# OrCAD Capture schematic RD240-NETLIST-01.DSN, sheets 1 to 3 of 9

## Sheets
1 9: size A3
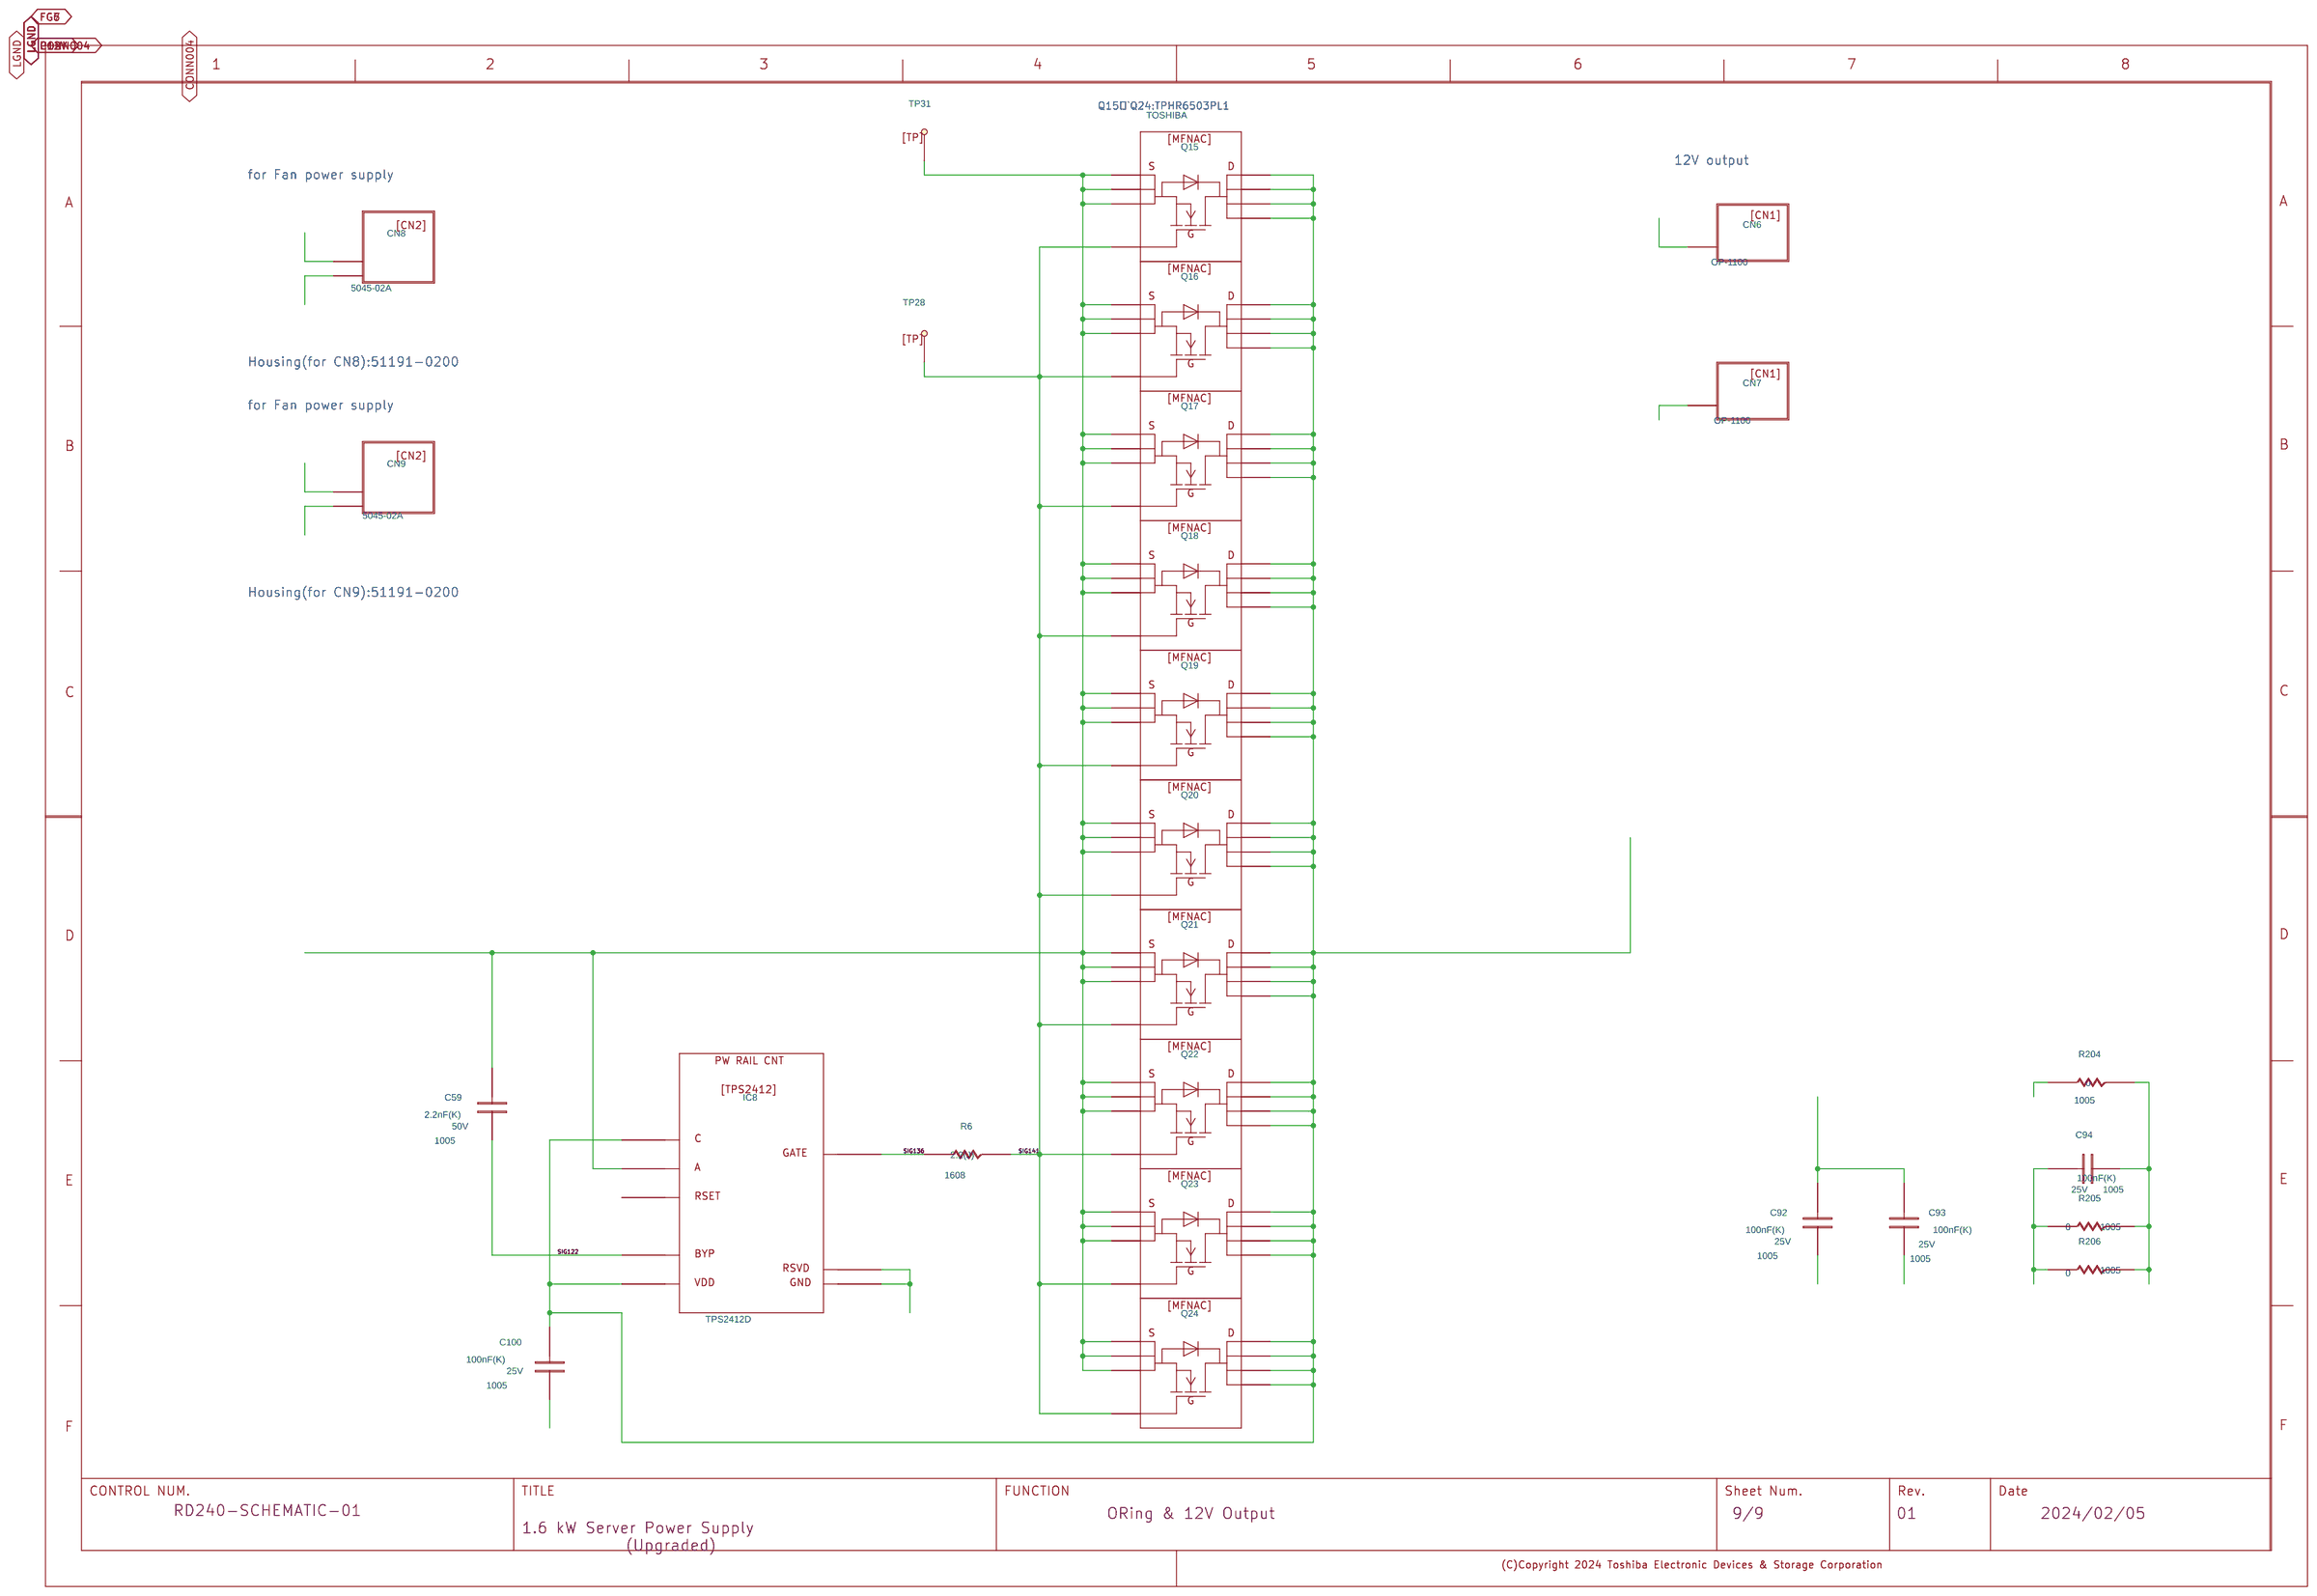
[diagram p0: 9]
2 8: size A3
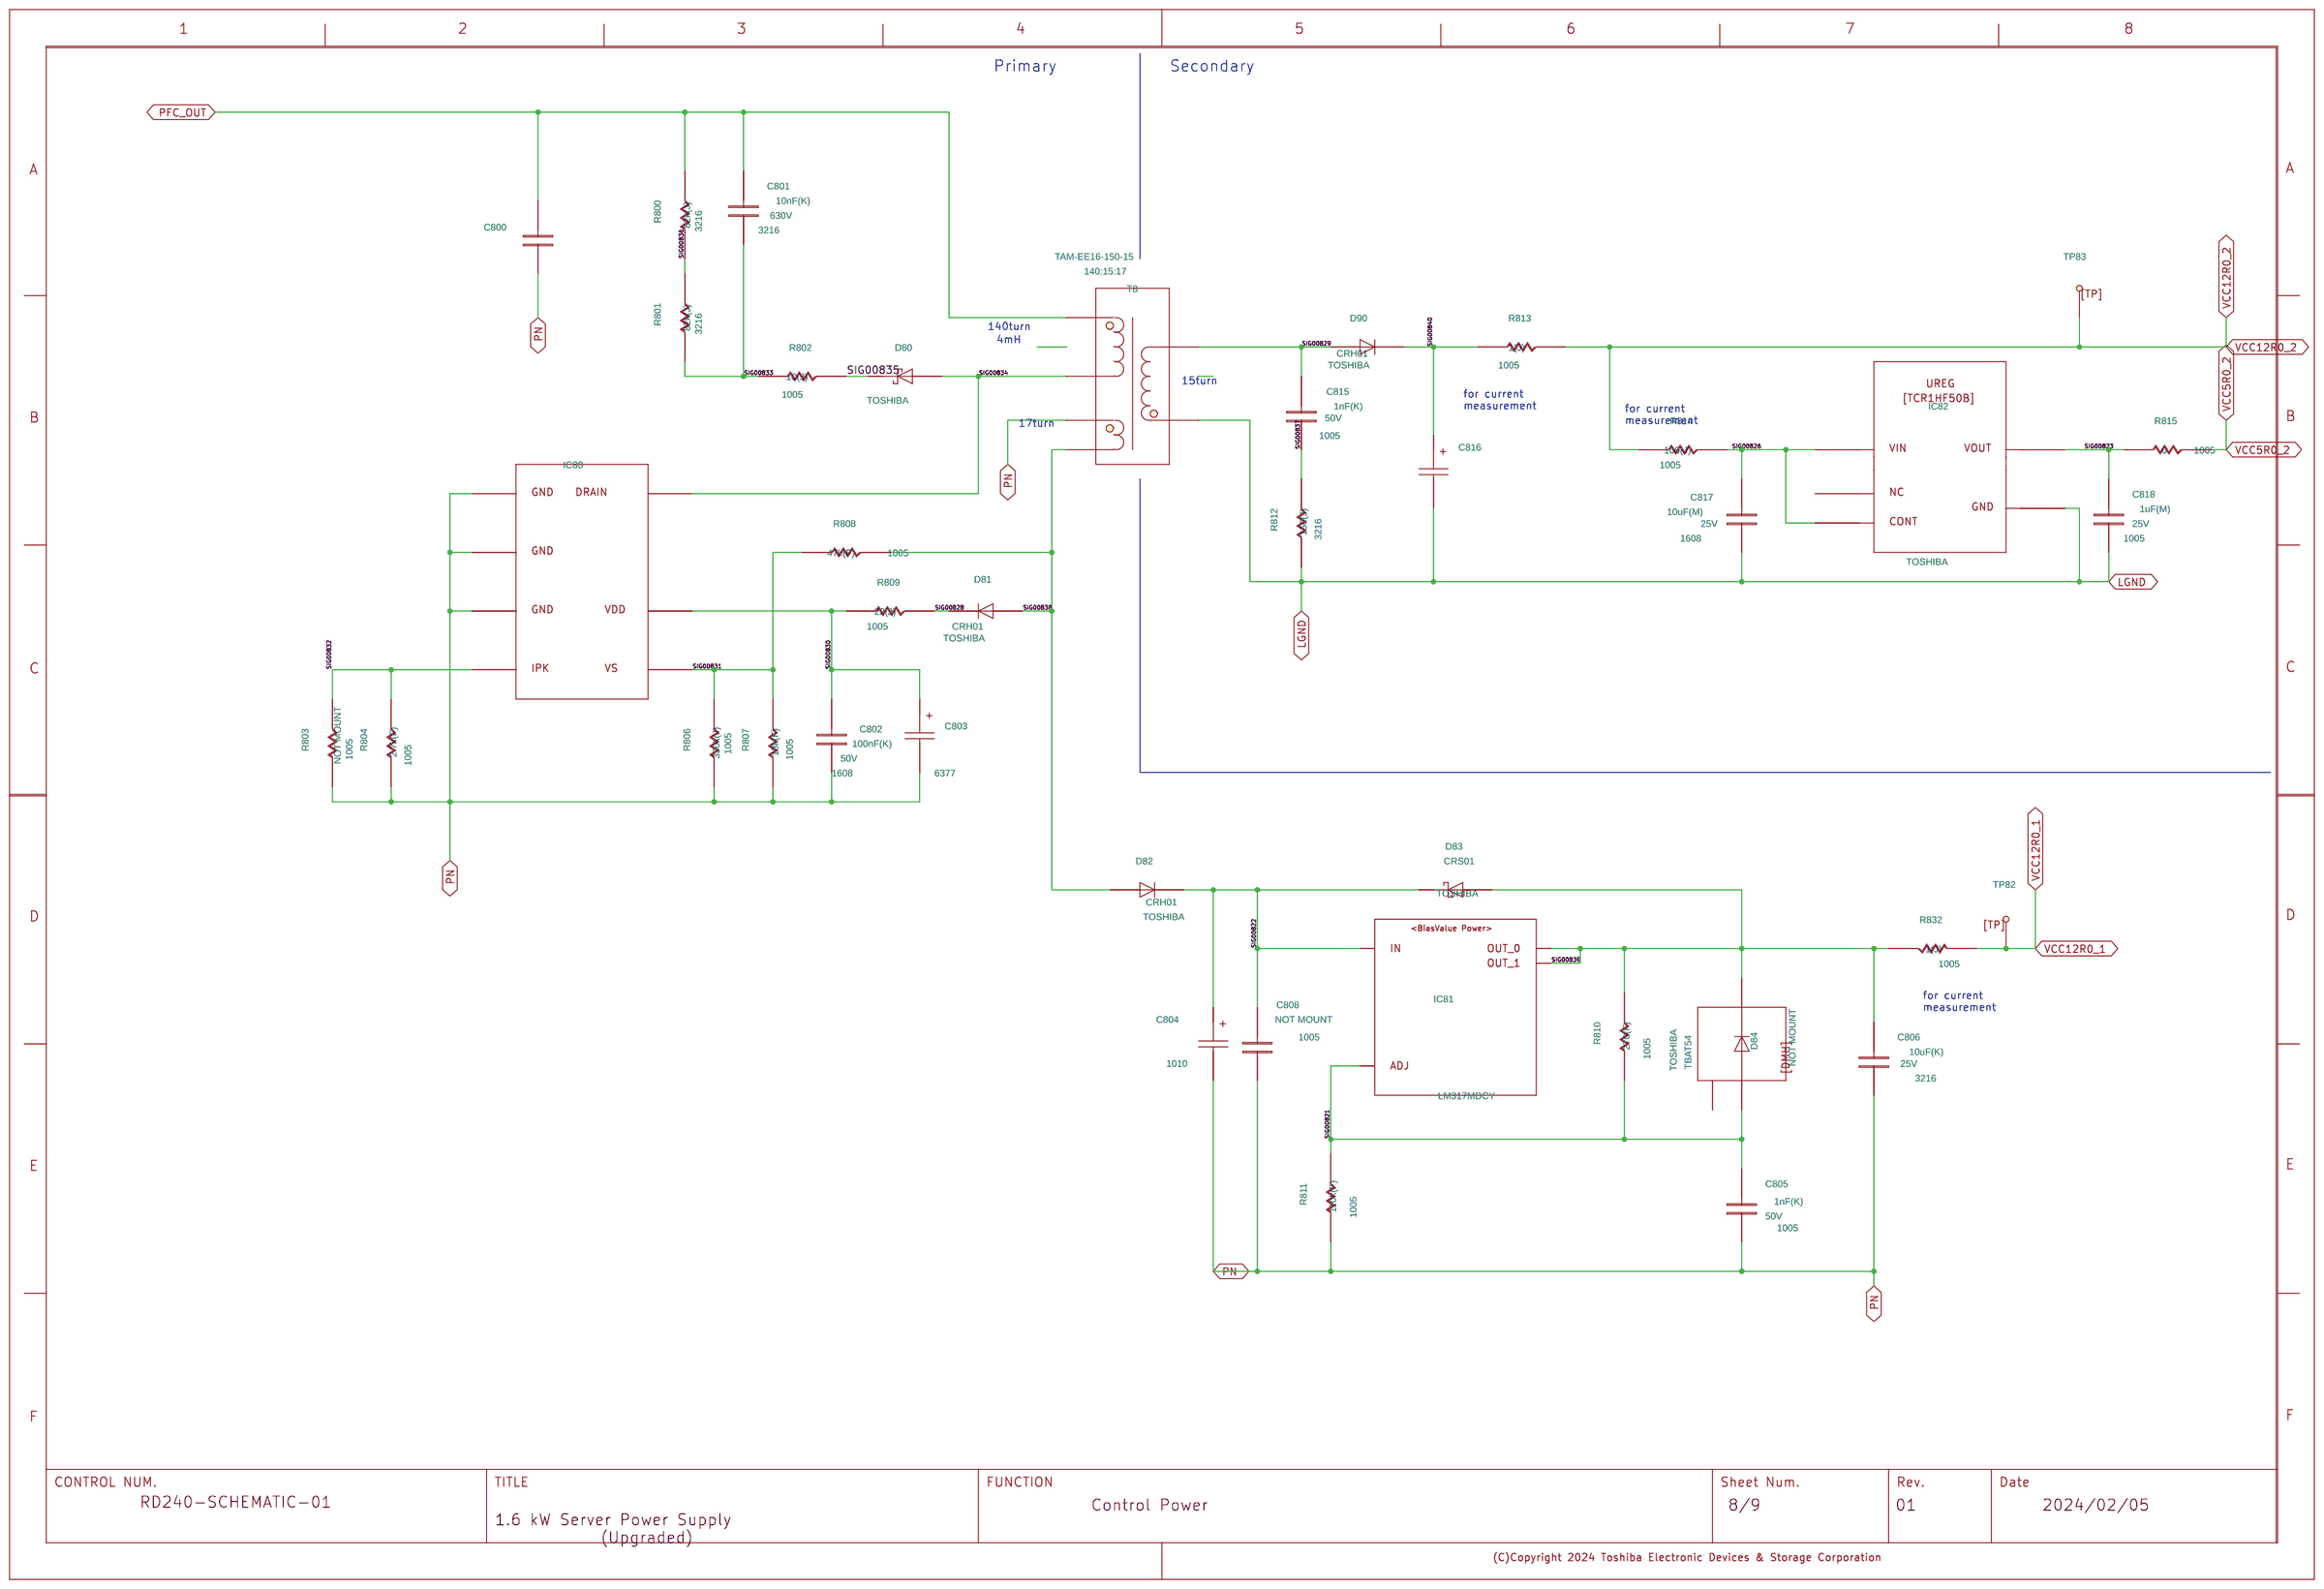
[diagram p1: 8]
3 7: size A3
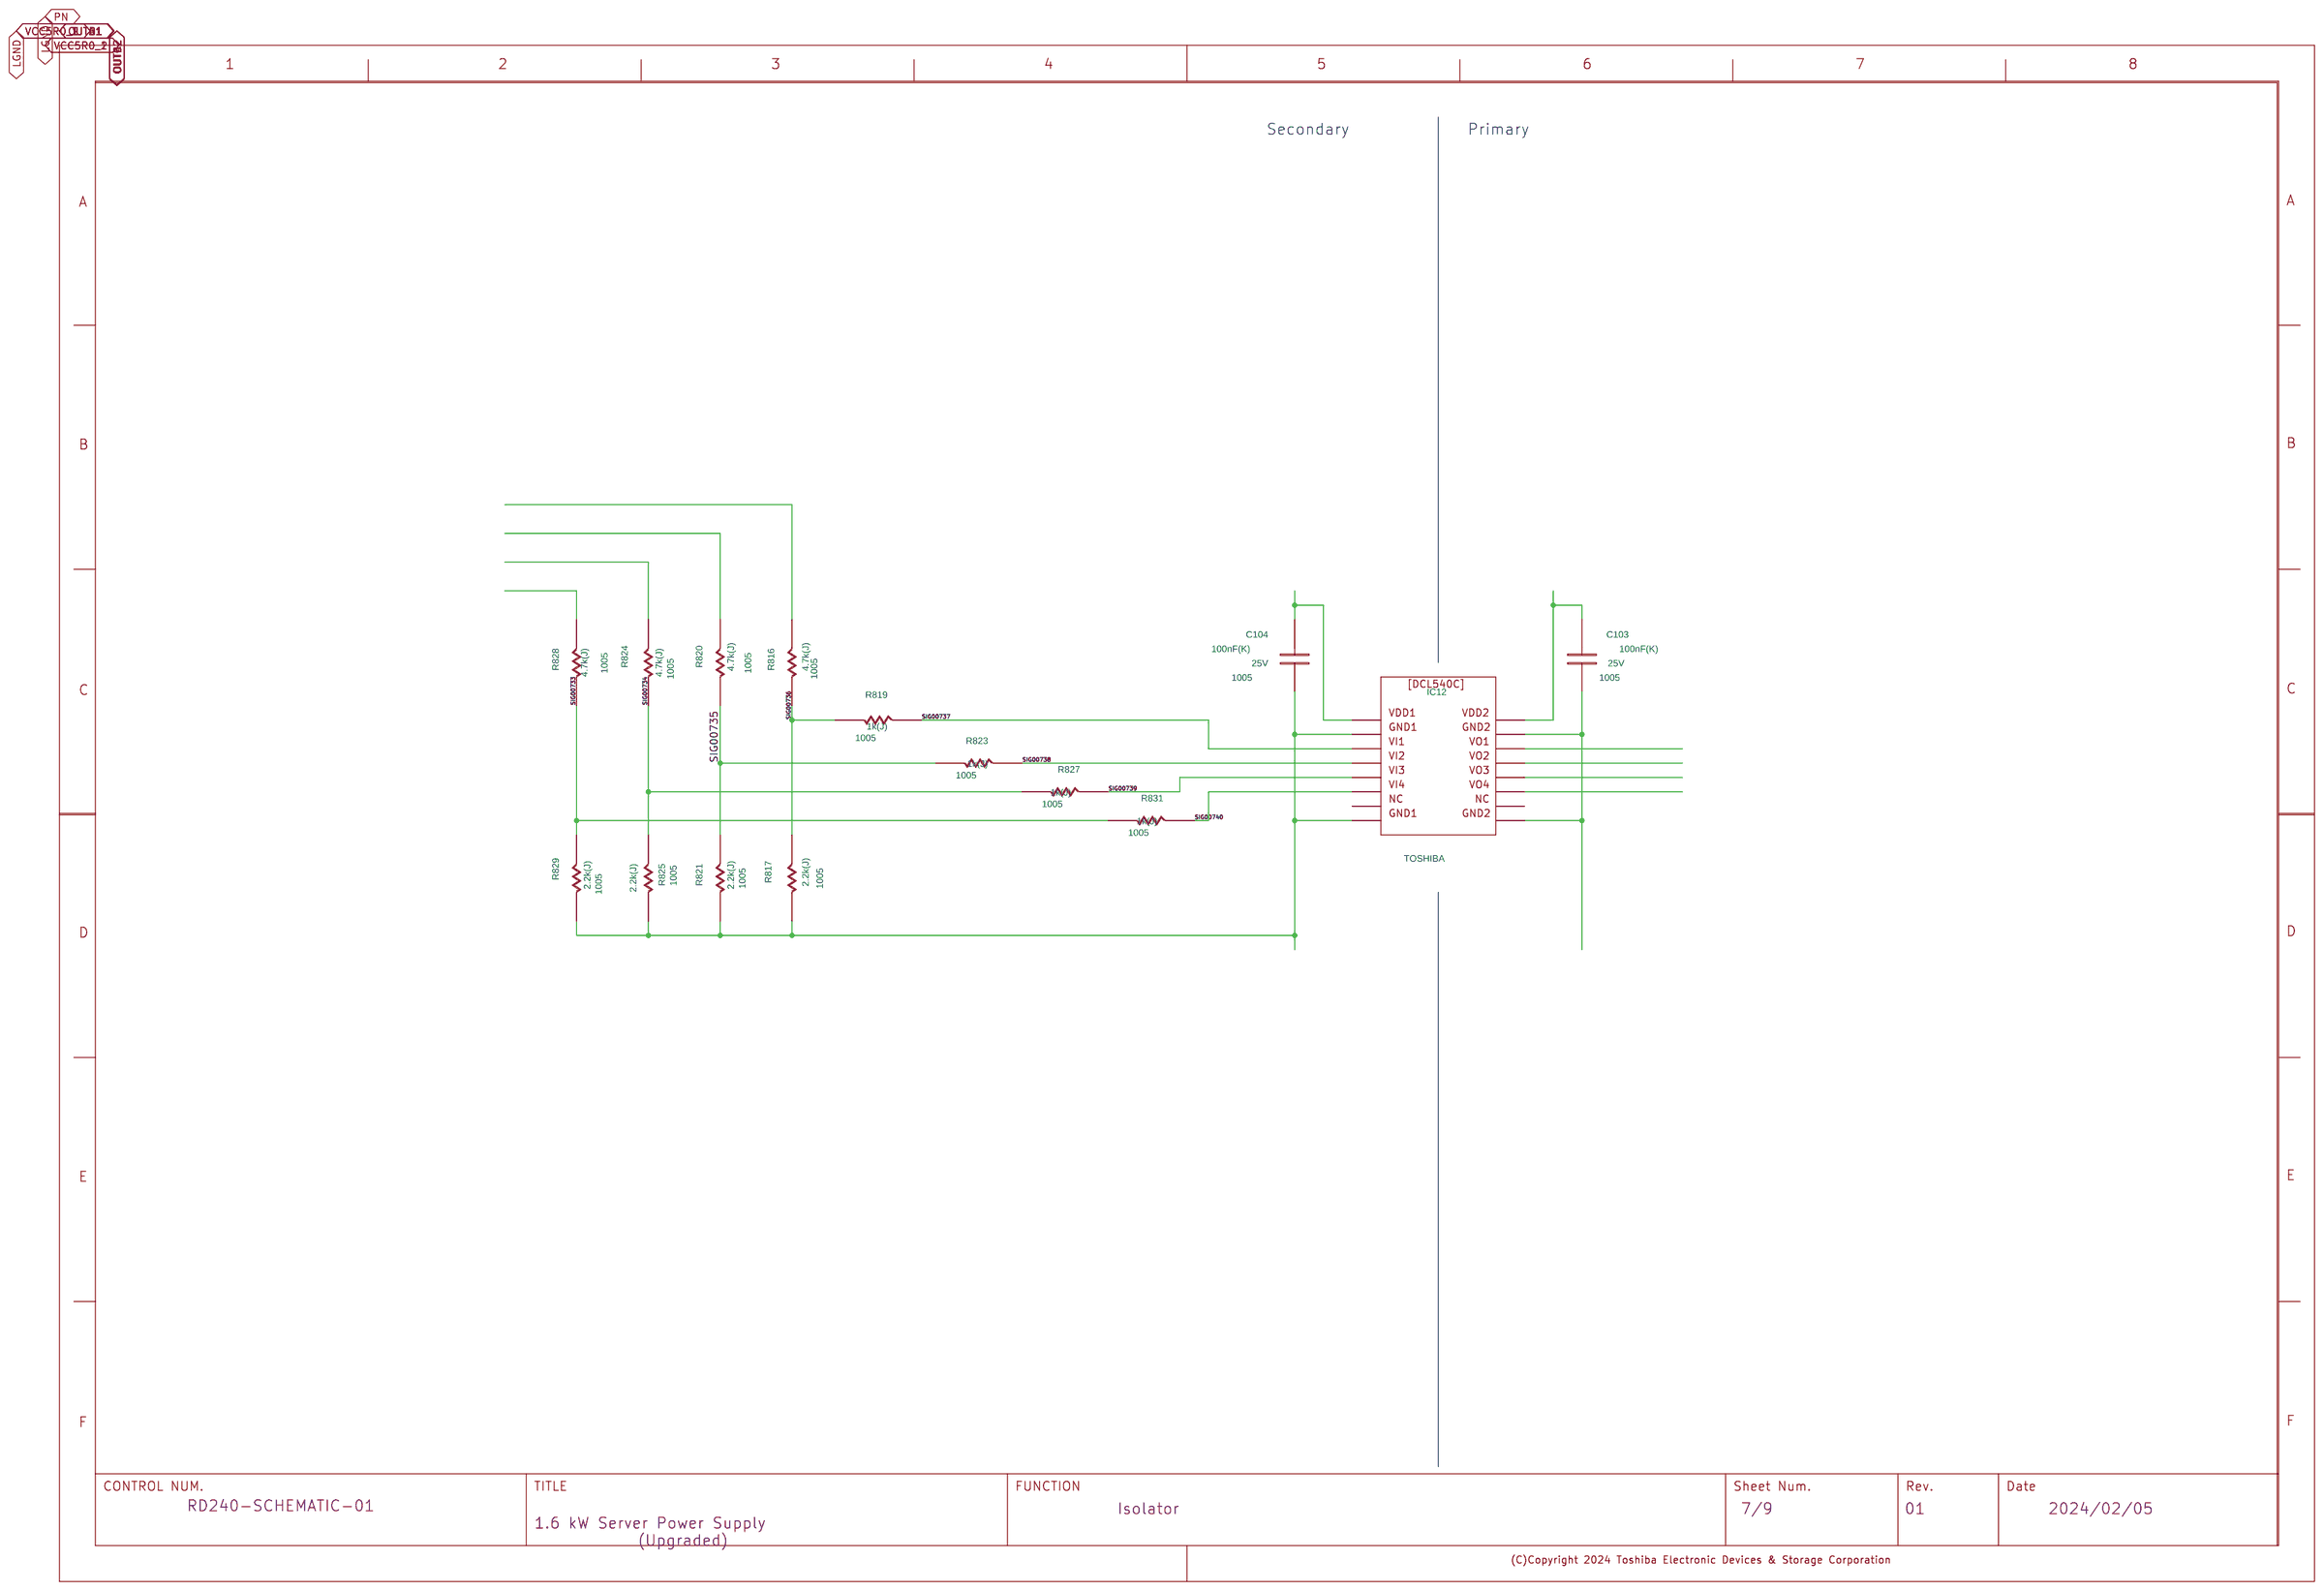
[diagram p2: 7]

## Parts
sheet 7
C103  C
C104  C
IC12  DCL540C01
R816  R
R817  R
R819  R
R820  R
R821  R
R823  R
R824  R
R825  R
R827  R
R828  R
R829  R
R831  R
U?#2  WAKU_DEF100
sheet 8
C800  ECWF6104JL
C801  C
C802  C
C803  EMLA350ARA220MF61G
C804  EMLA350ARA331MJA0G
C805  C
C806  C
C808  C
C815  C
C816  EMLA250ARA221MHA0G
C817  C
C818  C
D80  CRF03A
D81  D
D82  D
D83  SBD
D84  DMH
D90  D
IC80  UCC28910
IC81  LM317_TRANS  [DCY0004A_N]
IC82  TCR1HF50B
R800  R
R801  R
R802  R
R803  R
R804  R
R806  R
R807  R
R808  R
R809  R
R810  R
R811  R
R812  R
R813  R
R814  R
R815  R
R832  R
T8  YB_03317A
TP82  TP
TP83  TP
U?#1  WAKU_DEF100
sheet 9
C59  C
C92  C
C93  C
C94  C
C100  C
CN6  CN1
CN7  CN1
CN8  CN2
CN9  CN2
IC8  L2412
Q15  TPHR6503PL1_8PIN
Q16  TPHR6503PL1_8PIN
Q17  TPHR6503PL1_8PIN
Q18  TPHR6503PL1_8PIN
Q19  TPHR6503PL1_8PIN
Q20  TPHR6503PL1_8PIN
Q21  TPHR6503PL1_8PIN
Q22  TPHR6503PL1_8PIN
Q23  TPHR6503PL1_8PIN
Q24  TPHR6503PL1_8PIN
R6  R
R204  R
R205  R
R206  R
TP28  TP
TP31  TP
U?#9  WAKU_DEF100

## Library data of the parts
C103 = C: ADSCNVFLAG: ON; ADSCOMPONENTNAME: C_1005; ADSMODELNAME: s_GRM155R71E104KE14D; AUTHOR: sptcae13; CAPACITANCETOLE: K; CDMASTERCADCELG: KC0005; CHIPSIZE: 1005; COMP: PRT_52; COMPONENTTYPE: 4; DATE: 2024/01/31; FNLEADFREETHET1GT2GMCTH1: N_N_N; GCOUNT: 1; ICX_PART_MODEL: CON_100N; INSTANCENAME: cmp183; MAKER: TDK; MAXGCOUNT: 1; NOMINALCAPACITA: 100n; OUMECLASSIFICATION: ƒZƒ‰ƒ~ƒbƒNƒRƒ“ƒfƒ“ƒT; OUMEMAKER: MRT ºc»ì; OUMEMAKERKATAMEI: GRM155R71E104KE14D; QUADMODEL: CON_100N; RATEDVOLTAGE: 25; SAVECOUNT: 0; SIZECODESMD: 1005; SQ_PART_MODEL: CON_100N; TIME: 13:58:26; UPDATEDATE: 2024/01/31; UPDATETIME: 13:58:26; UPDATEUSER: sptcae13; VAL1: 100nF(K); VAL2: 25V; VAL3: C1005X7R1E104K050BB
C104 = C: ADSCNVFLAG: ON; ADSCOMPONENTNAME: C_1005; ADSMODELNAME: s_GRM155R71E104KE14D; AUTHOR: sptcae13; CAPACITANCETOLE: K; CDMASTERCADCELG: KC0005; CHIPSIZE: 1005; COMP: PRT_52; COMPONENTTYPE: 4; DATE: 2024/01/31; FNLEADFREETHET1GT2GMCTH1: N_N_N; GCOUNT: 1; ICX_PART_MODEL: CON_100N; INSTANCENAME: cmp178; MAKER: TDK; MAXGCOUNT: 1; NOMINALCAPACITA: 100n; OUMECLASSIFICATION: ƒZƒ‰ƒ~ƒbƒNƒRƒ“ƒfƒ“ƒT; OUMEMAKER: MRT ºc»ì; OUMEMAKERKATAMEI: GRM155R71E104KE14D; QUADMODEL: CON_100N; RATEDVOLTAGE: 25; SAVECOUNT: 0; SIZECODESMD: 1005; SQ_PART_MODEL: CON_100N; TIME: 13:58:26; UPDATEDATE: 2024/01/31; UPDATETIME: 13:58:26; UPDATEUSER: sptcae13; VAL1: 100nF(K); VAL2: 25V; VAL3: C1005X7R1E104K050BB
IC12 = DCL540C01: ALLGREEN: 0:O[; CDMASTERCADCELG: DI9G1D; COMPONENTTYPE: 4; FNAPPROVALRESUG: B:i(GREEN); FNCANCELLATIONG: 0:Žg—p‰Â; FNENVIRONMANTRG: 0:Žg—p–³; FNLEADFREETHET1GT2GMCTH1: 2_0_N; FUNCTION: FXD; GANSWERREV: 6; GCOUNT: 1; INSTANCENAME: cmp194; KIND: VRGL; MAXGCOUNT: 1; MOUNTINGFORMSMD: SMD; OUMECLASSIFICATION: M[^; OUMEMAKER: ROH [; OUMEMAKERKATAMEI: BH15LB1WG-TR; OUMEPARTTYPE: IC; PMPRODUCTSTYPEG: TV2; USERCOMPTEXT3: TOSHIBA
R816 = R: ADSMODELNAME: s_RC0402FR_071KL; ALLGREEN: 0:O[; CDMASTERCADCELG: KC0005; CHIPSIZE: 1608; COMPONENTTYPE: 4; FNAPPROVALRESUG: B:i(GREEN); FNCANCELLATIONG: 0:Žg—p‰Â; FNENVIRONMANTRG: 1:gpL(K§ÎÛO); FNLEADFREETHET1GT2GMCTH1: 2_2_N; GANSWERREV: 8; GCOUNT: 1; INSTANCENAME: cmp288; MAKER: PANASONIC; MAXGCOUNT: 1; MOUNTINGFORMSMD: SMD; NOMINALRESISTAN: 1K; OUMECLASSIFICATION: \ÊÀpÅèïRí; OUMEMAKER: YGO ƒ„ƒQƒI; OUMEMAKERKATAMEI: RC0402FR-071KL; PMPRODUCTSTYPEG: HD1; POWERRATING: 63m; QUADMODEL: RES_1K; RESISTANCETOLER: F; SAVECOUNT: 0; SIZECODESMD: 1005; VAL1: 4.7k(J); VAL2: 63mW; VAL3: RK73B1ERTTP472J
R817 = R: ADSMODELNAME: s_RC0402FR_071KL; ALLGREEN: 0:O[; CDMASTERCADCELG: KC0005; CHIPSIZE: 1608; COMPONENTTYPE: 4; FNAPPROVALRESUG: B:i(GREEN); FNCANCELLATIONG: 0:Žg—p‰Â; FNENVIRONMANTRG: 1:gpL(K§ÎÛO); FNLEADFREETHET1GT2GMCTH1: 2_2_N; GANSWERREV: 8; GCOUNT: 1; INSTANCENAME: cmp284; MAKER: PANASONIC; MAXGCOUNT: 1; MOUNTINGFORMSMD: SMD; NOMINALRESISTAN: 1K; OUMECLASSIFICATION: \ÊÀpÅèïRí; OUMEMAKER: YGO ƒ„ƒQƒI; OUMEMAKERKATAMEI: RC0402FR-071KL; PMPRODUCTSTYPEG: HD1; POWERRATING: 63m; QUADMODEL: RES_1K; RESISTANCETOLER: F; SAVECOUNT: 0; SIZECODESMD: 1005; VAL1: 2.2k(J); VAL2: 63mW; VAL3: RK73B1ERTTP222J
R819 = R: ADSMODELNAME: s_RC0402FR_071KL; ALLGREEN: 0:O[; CDMASTERCADCELG: KC0005; CHIPSIZE: 1608; COMPONENTTYPE: 4; FNAPPROVALRESUG: B:i(GREEN); FNCANCELLATIONG: 0:Žg—p‰Â; FNENVIRONMANTRG: 1:gpL(K§ÎÛO); FNLEADFREETHET1GT2GMCTH1: 2_2_N; GANSWERREV: 8; GCOUNT: 1; INSTANCENAME: cmp222; MAKER: PANASONIC; MAXGCOUNT: 1; MOUNTINGFORMSMD: SMD; NOMINALRESISTAN: 1K; OUMECLASSIFICATION: \ÊÀpÅèïRí; OUMEMAKER: YGO ƒ„ƒQƒI; OUMEMAKERKATAMEI: RC0402FR-071KL; PMPRODUCTSTYPEG: HD1; POWERRATING: 63m; QUADMODEL: RES_1K; RESISTANCETOLER: F; SAVECOUNT: 0; SIZECODESMD: 1005; VAL1: 1k(J); VAL2: 63mW; VAL3: RK73K1ETP102J
R820 = R: ADSMODELNAME: s_RC0402FR_071KL; ALLGREEN: 0:O[; CDMASTERCADCELG: KC0005; CHIPSIZE: 1608; COMPONENTTYPE: 4; FNAPPROVALRESUG: B:i(GREEN); FNCANCELLATIONG: 0:Žg—p‰Â; FNENVIRONMANTRG: 1:gpL(K§ÎÛO); FNLEADFREETHET1GT2GMCTH1: 2_2_N; GANSWERREV: 8; GCOUNT: 1; INSTANCENAME: cmp291; MAKER: PANASONIC; MAXGCOUNT: 1; MOUNTINGFORMSMD: SMD; NOMINALRESISTAN: 1K; OUMECLASSIFICATION: \ÊÀpÅèïRí; OUMEMAKER: YGO ƒ„ƒQƒI; OUMEMAKERKATAMEI: RC0402FR-071KL; PMPRODUCTSTYPEG: HD1; POWERRATING: 63m; QUADMODEL: RES_1K; RESISTANCETOLER: F; SAVECOUNT: 0; SIZECODESMD: 1005; VAL1: 4.7k(J); VAL2: 63mW; VAL3: RK73B1ERTTP472J
R821 = R: ADSMODELNAME: s_RC0402FR_071KL; ALLGREEN: 0:O[; CDMASTERCADCELG: KC0005; CHIPSIZE: 1608; COMPONENTTYPE: 4; FNAPPROVALRESUG: B:i(GREEN); FNCANCELLATIONG: 0:Žg—p‰Â; FNENVIRONMANTRG: 1:gpL(K§ÎÛO); FNLEADFREETHET1GT2GMCTH1: 2_2_N; GANSWERREV: 8; GCOUNT: 1; INSTANCENAME: cmp285; MAKER: PANASONIC; MAXGCOUNT: 1; MOUNTINGFORMSMD: SMD; NOMINALRESISTAN: 1K; OUMECLASSIFICATION: \ÊÀpÅèïRí; OUMEMAKER: YGO ƒ„ƒQƒI; OUMEMAKERKATAMEI: RC0402FR-071KL; PMPRODUCTSTYPEG: HD1; POWERRATING: 63m; QUADMODEL: RES_1K; RESISTANCETOLER: F; SAVECOUNT: 0; SIZECODESMD: 1005; VAL1: 2.2k(J); VAL2: 63mW; VAL3: RK73B1ERTTP222J
R823 = R: ADSMODELNAME: s_RC0402FR_071KL; ALLGREEN: 0:O[; CDMASTERCADCELG: KC0005; CHIPSIZE: 1608; COMPONENTTYPE: 4; FNAPPROVALRESUG: B:i(GREEN); FNCANCELLATIONG: 0:Žg—p‰Â; FNENVIRONMANTRG: 1:gpL(K§ÎÛO); FNLEADFREETHET1GT2GMCTH1: 2_2_N; GANSWERREV: 8; GCOUNT: 1; INSTANCENAME: cmp231; MAKER: PANASONIC; MAXGCOUNT: 1; MOUNTINGFORMSMD: SMD; NOMINALRESISTAN: 1K; OUMECLASSIFICATION: \ÊÀpÅèïRí; OUMEMAKER: YGO ƒ„ƒQƒI; OUMEMAKERKATAMEI: RC0402FR-071KL; PMPRODUCTSTYPEG: HD1; POWERRATING: 63m; QUADMODEL: RES_1K; RESISTANCETOLER: F; SAVECOUNT: 0; SIZECODESMD: 1005; VAL1: 1k(J); VAL2: 63mW; VAL3: RK73K1ETP102J
R824 = R: ADSMODELNAME: s_RC0402FR_071KL; ALLGREEN: 0:O[; CDMASTERCADCELG: KC0005; CHIPSIZE: 1608; COMPONENTTYPE: 4; FNAPPROVALRESUG: B:i(GREEN); FNCANCELLATIONG: 0:Žg—p‰Â; FNENVIRONMANTRG: 1:gpL(K§ÎÛO); FNLEADFREETHET1GT2GMCTH1: 2_2_N; GANSWERREV: 8; GCOUNT: 1; INSTANCENAME: cmp289; MAKER: PANASONIC; MAXGCOUNT: 1; MOUNTINGFORMSMD: SMD; NOMINALRESISTAN: 1K; OUMECLASSIFICATION: \ÊÀpÅèïRí; OUMEMAKER: YGO ƒ„ƒQƒI; OUMEMAKERKATAMEI: RC0402FR-071KL; PMPRODUCTSTYPEG: HD1; POWERRATING: 63m; QUADMODEL: RES_1K; RESISTANCETOLER: F; SAVECOUNT: 0; SIZECODESMD: 1005; VAL1: 4.7k(J); VAL2: 63mW; VAL3: RK73B1ERTTP472J
R825 = R: ADSMODELNAME: s_RC0402FR_071KL; ALLGREEN: 0:O[; CDMASTERCADCELG: KC0005; CHIPSIZE: 1608; COMPONENTTYPE: 4; FNAPPROVALRESUG: B:i(GREEN); FNCANCELLATIONG: 0:Žg—p‰Â; FNENVIRONMANTRG: 1:gpL(K§ÎÛO); FNLEADFREETHET1GT2GMCTH1: 2_2_N; GANSWERREV: 8; GCOUNT: 1; INSTANCENAME: cmp286; MAKER: PANASONIC; MAXGCOUNT: 1; MOUNTINGFORMSMD: SMD; NOMINALRESISTAN: 1K; OUMECLASSIFICATION: \ÊÀpÅèïRí; OUMEMAKER: YGO ƒ„ƒQƒI; OUMEMAKERKATAMEI: RC0402FR-071KL; PMPRODUCTSTYPEG: HD1; POWERRATING: 63m; QUADMODEL: RES_1K; RESISTANCETOLER: F; SAVECOUNT: 0; SIZECODESMD: 1005; VAL1: 2.2k(J); VAL2: 63mW; VAL3: RK73B1ERTTP222J
R827 = R: ADSMODELNAME: s_RC0402FR_071KL; ALLGREEN: 0:O[; CDMASTERCADCELG: KC0005; CHIPSIZE: 1608; COMPONENTTYPE: 4; FNAPPROVALRESUG: B:i(GREEN); FNCANCELLATIONG: 0:Žg—p‰Â; FNENVIRONMANTRG: 1:gpL(K§ÎÛO); FNLEADFREETHET1GT2GMCTH1: 2_2_N; GANSWERREV: 8; GCOUNT: 1; INSTANCENAME: cmp240; MAKER: PANASONIC; MAXGCOUNT: 1; MOUNTINGFORMSMD: SMD; NOMINALRESISTAN: 1K; OUMECLASSIFICATION: \ÊÀpÅèïRí; OUMEMAKER: YGO ƒ„ƒQƒI; OUMEMAKERKATAMEI: RC0402FR-071KL; PMPRODUCTSTYPEG: HD1; POWERRATING: 63m; QUADMODEL: RES_1K; RESISTANCETOLER: F; SAVECOUNT: 0; SIZECODESMD: 1005; VAL1: 1k(J); VAL2: 63mW; VAL3: RK73K1ETP102J
R828 = R: ADSMODELNAME: s_RC0402FR_071KL; ALLGREEN: 0:O[; CDMASTERCADCELG: KC0005; CHIPSIZE: 1608; COMPONENTTYPE: 4; FNAPPROVALRESUG: B:i(GREEN); FNCANCELLATIONG: 0:Žg—p‰Â; FNENVIRONMANTRG: 1:gpL(K§ÎÛO); FNLEADFREETHET1GT2GMCTH1: 2_2_N; GANSWERREV: 8; GCOUNT: 1; INSTANCENAME: cmp290; MAKER: PANASONIC; MAXGCOUNT: 1; MOUNTINGFORMSMD: SMD; NOMINALRESISTAN: 1K; OUMECLASSIFICATION: \ÊÀpÅèïRí; OUMEMAKER: YGO ƒ„ƒQƒI; OUMEMAKERKATAMEI: RC0402FR-071KL; PMPRODUCTSTYPEG: HD1; POWERRATING: 63m; QUADMODEL: RES_1K; RESISTANCETOLER: F; SAVECOUNT: 0; SIZECODESMD: 1005; VAL1: 4.7k(J); VAL2: 63mW; VAL3: RK73B1ERTTP472J
R829 = R: ADSMODELNAME: s_RC0402FR_071KL; ALLGREEN: 0:O[; CDMASTERCADCELG: KC0005; CHIPSIZE: 1608; COMPONENTTYPE: 4; FNAPPROVALRESUG: B:i(GREEN); FNCANCELLATIONG: 0:Žg—p‰Â; FNENVIRONMANTRG: 1:gpL(K§ÎÛO); FNLEADFREETHET1GT2GMCTH1: 2_2_N; GANSWERREV: 8; GCOUNT: 1; INSTANCENAME: cmp287; MAKER: PANASONIC; MAXGCOUNT: 1; MOUNTINGFORMSMD: SMD; NOMINALRESISTAN: 1K; OUMECLASSIFICATION: \ÊÀpÅèïRí; OUMEMAKER: YGO ƒ„ƒQƒI; OUMEMAKERKATAMEI: RC0402FR-071KL; PMPRODUCTSTYPEG: HD1; POWERRATING: 63m; QUADMODEL: RES_1K; RESISTANCETOLER: F; SAVECOUNT: 0; SIZECODESMD: 1005; VAL1: 2.2k(J); VAL2: 63mW; VAL3: RK73B1ERTTP222J
R831 = R: ADSMODELNAME: s_RC0402FR_071KL; ALLGREEN: 0:O[; CDMASTERCADCELG: KC0005; CHIPSIZE: 1608; COMPONENTTYPE: 4; FNAPPROVALRESUG: B:i(GREEN); FNCANCELLATIONG: 0:Žg—p‰Â; FNENVIRONMANTRG: 1:gpL(K§ÎÛO); FNLEADFREETHET1GT2GMCTH1: 2_2_N; GANSWERREV: 8; GCOUNT: 1; INSTANCENAME: cmp249; MAKER: PANASONIC; MAXGCOUNT: 1; MOUNTINGFORMSMD: SMD; NOMINALRESISTAN: 1K; OUMECLASSIFICATION: \ÊÀpÅèïRí; OUMEMAKER: YGO ƒ„ƒQƒI; OUMEMAKERKATAMEI: RC0402FR-071KL; PMPRODUCTSTYPEG: HD1; POWERRATING: 63m; QUADMODEL: RES_1K; RESISTANCETOLER: F; SAVECOUNT: 0; SIZECODESMD: 1005; VAL1: 1k(J); VAL2: 63mW; VAL3: RK73K1ETP102J
U?#2 = WAKU_DEF100: COMPONENTTYPE: 2; DATE: 2024/02/05; DESIGNED: TOSHIBA; DRAWINGNUMBER: RD240-SCHEMATIC-01; FUNCTION: Isolator; INSTANCENAME: cmp174; PAGENUMBER: 7; REVISION: 01; SHEETNUMBER: 7/9; SHTSAVECOUNT: 58; TITLE: 1.6 kW Server Power Supply / (Upgraded); UPDATEDATE: 2024/02/07; UPDATETIME: 09:49:39; UPDATEUSER: t5459927
C800 = ECWF6104JL: ALLGREEN: 1:ñO[; CAPACITANCETOLE: K; CDMASTERCADCELG: DC0272; COMPONENTTYPE: 4; FNAPPROVALRESUG: 4:i; FNCANCELLATIONG: 0:Žg—p‰Â; FNENVIRONMANTRG: 2:Žg—p—L(ŠúŒÀ•t); FNLEADFREETHET1GT2GMCTH1: 9_N_N; GCOUNT: 1; INSTANCENAME: cmp295; MAXGCOUNT: 1; NOMINALCAPACITA: 100n; OUMECLASSIFICATION: ƒtƒBƒ‹ƒƒRƒ“ƒfƒ“ƒT; OUMEMAKER: NTC ƒjƒ`ƒRƒ“; OUMEMAKERKATAMEI: QXJ2J104KTPT; OUMEPARTTYPE: C; QUADMODEL: CON_100N; RATEDVOLTAGE: 630; SIZECODESMD: DIP
C801 = C: AUTHOR: sptcae13; COMP: PRT_46; COMPONENTTYPE: 4; DATE: 2024/01/31; INSTANCENAME: cmp308; SAVECOUNT: 0; SIZECODESMD: 3216; TIME: 13:58:26; UPDATEDATE: 2024/01/31; UPDATETIME: 13:58:26; UPDATEUSER: sptcae13; VAL1: 10nF(K); VAL2: 630V; VAL3: GCM31BR72J103KX01
C802 = C: AUTHOR: sptcae13; COMP: PRT_48; COMPONENTTYPE: 4; DATE: 2024/01/31; INSTANCENAME: cmp289; SAVECOUNT: 0; SIZECODESMD: 1608; TIME: 13:58:26; UPDATEDATE: 2024/01/31; UPDATETIME: 13:58:26; UPDATEUSER: sptcae13; VAL1: 100nF(K); VAL2: 50V; VAL3: GCM188R11H104KA42D
C803 = EMLA350ARA220MF61G: ALLGREEN: 1:ñO[; CAPACITANCETOLE: M; CDMASTERCADCELG: DC843R; COMPONENTTYPE: 4; FNAPPROVALRESUG: 4:i; FNCANCELLATIONG: 0:Žg—p‰Â; FNENVIRONMANTRG: 0:Žg—p–³; FNLEADFREETHET1GT2GMCTH1: 2_0_N; GCOUNT: 1; INSTANCENAME: cmp313; MAXGCOUNT: 1; NOMINALCAPACITA: 220u; OUMECLASSIFICATION: ƒAƒ‹ƒ~“d‰ðƒRƒ“ƒfƒ“ƒT; OUMEMAKER: NAE pi\jbNGNgjbNfoCX; OUMEMAKERKATAMEI: EEEFK1C221XP; OUMEPARTTYPE: C; PMPRODUCTSTYPEG: PJ1-TV2; QUADMODEL: CON_220U; RATEDVOLTAGE: 16; SIZECODESMD: 6377
C804 = EMLA350ARA331MJA0G: ALLGREEN: 1:ñO[; CAPACITANCETOLE: M; CDMASTERCADCELG: DC845R; COMPONENTTYPE: 4; FNAPPROVALRESUG: 4:i; FNCANCELLATIONG: 0:Žg—p‰Â; FNENVIRONMANTRG: N:¢²¸; FNLEADFREETHET1GT2GMCTH1: 0_0_N; GCOUNT: 1; INSTANCENAME: cmp232; MAXGCOUNT: 1; NOMINALCAPACITA: 470u; OUMECLASSIFICATION: ƒAƒ‹ƒ~“d‰ðƒRƒ“ƒfƒ“ƒT; OUMEMAKER: NAE pi\jbNGNgjbNfoCX; OUMEMAKERKATAMEI: EEVHB1A471P; OUMEPARTTYPE: C; QUADMODEL: CON_470U; RATEDVOLTAGE: 10; SIZECODESMD: 1010
C805 = C: AUTHOR: sptcae13; COMP: PRT_52; COMPONENTTYPE: 4; DATE: 2024/01/31; INSTANCENAME: cmp240; SAVECOUNT: 0; SIZECODESMD: 1005; TIME: 13:58:26; UPDATEDATE: 2024/01/31; UPDATETIME: 13:58:26; UPDATEUSER: sptcae13; VAL1: 1nF(K); VAL2: 50V; VAL3: UMK105BJ102KV-F
C806 = C: AUTHOR: sptcae13; COMP: PRT_46; COMPONENTTYPE: 4; DATE: 2024/01/31; INSTANCENAME: cmp241; SAVECOUNT: 0; SIZECODESMD: 3216; TIME: 13:58:26; UPDATEDATE: 2024/01/31; UPDATETIME: 13:58:26; UPDATEUSER: sptcae13; VAL1: 10uF(K); VAL2: 25V; VAL3: TMK316BJ106KL-T
C808 = C: AUTHOR: sptcae13; COMP: PRT_52; COMPONENTTYPE: 4; DATE: 2024/01/31; INSTANCENAME: cmp235; NOTMOUNT: NOT MOUNT; SAVECOUNT: 0; SIZECODESMD: 1005; TIME: 13:58:26; UPDATEDATE: 2024/01/31; UPDATETIME: 13:58:26; UPDATEUSER: sptcae13; VAL1: 2.2nF(K); VAL2: 50V; VAL3: UMK105BJ222KV-F
C815 = C: AUTHOR: sptcae13; COMP: PRT_52; COMPONENTTYPE: 4; DATE: 2024/01/31; INSTANCENAME: cmp342; SAVECOUNT: 0; SIZECODESMD: 1005; TIME: 13:58:26; UPDATEDATE: 2024/01/31; UPDATETIME: 13:58:26; UPDATEUSER: sptcae13; VAL1: 1nF(K); VAL2: 50V; VAL3: UMK105BJ102KV-F
C816 = EMLA250ARA221MHA0G: ALLGREEN: N:¢²¸; CAPACITANCETOLE: M; CDMASTERCADCELG: DC837R; COMPONENTTYPE: 4; FNAPPROVALRESUG: 0:”­”Ô‚Ì‚Ý; FNCANCELLATIONG: 0:Žg—p‰Â; FNENVIRONMANTRG: N:¢²¸; FNLEADFREETHET1GT2GMCTH1: N_N_N; GCOUNT: 1; INSTANCENAME: cmp293; MAXGCOUNT: 1; NOMINALCAPACITA: 47u; OUMECLASSIFICATION: ƒAƒ‹ƒ~“d‰ðƒRƒ“ƒfƒ“ƒT; OUMEMAKER: CHM “ú–{ƒPƒ~ƒRƒ“; OUMEMAKERKATAMEI: EMVH500ADA470MHA0G; OUMEPARTTYPE: C; PMPRODUCTSTYPEG: DME; QUADMODEL: CON_47U; RATEDVOLTAGE: 50; SIZECODESMD: 810
C817 = C: ADSMODELNAME: s_ZRB18AR61E106ME01L; AUTHOR: sptcae13; CAPACITANCETOLE: M; CDMASTERCADCELG: KC0167; CHIPSIZE: 1608; COMP: PRT_48; COMPONENTTYPE: 4; DATE: 2024/01/31; FNLEADFREETHET1GT2GMCTH1: N_N_N; GCOUNT: 1; INSTANCENAME: cmp261; MAKER: TDK; MAXGCOUNT: 1; NOMINALCAPACITA: 10u; OUMECLASSIFICATION: ƒZƒ‰ƒ~ƒbƒNƒRƒ“ƒfƒ“ƒT; OUMEMAKER: MRT ºc»ì; OUMEMAKERKATAMEI: ZRB18AR61E106ME01L; QUADMODEL: CON_10U; RATEDVOLTAGE: 25; SAVECOUNT: 0; SIZECODESMD: 1608; TIME: 13:58:26; UPDATEDATE: 2024/01/31; UPDATETIME: 13:58:26; UPDATEUSER: sptcae13; VAL1: 10uF(M); VAL2: 25V; VAL3: C1608X5R1E106M080AC
C818 = C: ADSCNVFLAG: ON; ADSCOMPONENTNAME: C_1608; ADSMODELNAME: s_GRM185B31E105KA12D; AUTHOR: sptcae13; CAPACITANCETOLE: K; CDMASTERCADCELG: KC0008; CHIPSIZE: 1005; COMP: PRT_52; COMPONENTTYPE: 4; DATE: 2024/01/31; FNLEADFREETHET1GT2GMCTH1: N_N_N; GCOUNT: 1; ICX_PART_MODEL: CON_1U; INSTANCENAME: cmp263; MAKER: TDK; MAXGCOUNT: 1; NOMINALCAPACITA: 1u; OUMECLASSIFICATION: ƒZƒ‰ƒ~ƒbƒNƒRƒ“ƒfƒ“ƒT; OUMEMAKER: MRT ºc»ì; OUMEMAKERKATAMEI: GRM185B31E105KA12D; PMPRODUCTSTYPEG: HD1; QUADMODEL: CON_1U; RATEDVOLTAGE: 25; SAVECOUNT: 0; SIZECODESMD: 1005; SQ_PART_MODEL: CON_1U; TEMPCHARACTERI2: B; TIME: 13:58:26; UPDATEDATE: 2024/01/31; UPDATETIME: 13:58:26; UPDATEUSER: sptcae13; VAL1: 1uF(M); VAL2: 25V; VAL3: C1005X5R1E105M050BC
D80 = CRF03A: ADSMODELNAME: s_CRS01_TE85R_Q_; ALLGREEN: N:¢²¸; CDMASTERCADCELG: MMK0167; COMPONENTTYPE: 4; FNAPPROVALRESUG: 5:bè(KR[h); FNCANCELLATIONG: 0:Žg—p‰Â; FNENVIRONMANTRG: N:¢²¸; FNLEADFREETHET1GT2GMCTH1: N_N_N; FORWARDVOLTAGEM: 0; GCOUNT: 1; INSTANCENAME: cmp299; MAXAVERAGEFORWA: 1; MAXGCOUNT: 1; MAXREPETITIVEPE: 30; MAXREVERSEVOLTA: 0; MOUNTINGFORMSMD: SMD; OUMECLASSIFICATION: ¬p®¬fq/VbgLoA_CI[h; OUMEMAKER: TSB “ŒŽÅ; OUMEMAKERKATAMEI: CRS01(TE85R,Q); OUMEPARTTYPE: D; PEAKFORWARDVOLT: 360m; REVERSECURRENT: 1.5m; USERCOMPTEXT3: TOSHIBA; ZENERVOLTAGEMAX: 0; ZENERVOLTAGEMIN: 0
D81 = D: ADSCNVFLAG: ON; ADSCOMPONENTNAME: D_D; ADSMODELNAME: s_CRH01_TE85L_AST_Q_; ALLGREEN: N:¢²¸; AUTHOR: sptcae13; CDMASTERCADCELG: MMK0167; COMP: GDM420000387; COMPONENTTYPE: 4; DATE: 2024/01/31; FNAPPROVALRESUG: 0:”­”Ô‚Ì‚Ý; FNCANCELLATIONG: 0:Žg—p‰Â; FNENVIRONMANTRG: N:¢²¸; FNLEADFREETHET1GT2GMCTH1: N_N_N; FORWARDVOLTAGEM: 0; FUNCN: GDM420000387; GATENO: 1; GCOUNT: 1; INSTANCENAME: cmp301; MAXAVERAGEFORWA: 1; MAXGCOUNT: 1; MAXREPETITIVEPE: 200; MAXREVERSEVOLTA: 0; MOUNTINGFORMSMD: SMD; OUMECLASSIFICATION: ¬p®¬fq/VbgLoA_CI[h; OUMEMAKER: TSB “ŒŽÅ; OUMEMAKERKATAMEI: CRH01(TE85L,AST,Q); PEAKFORWARDVOLT: 0; PMPRODUCTSTYPEG: DME; REVERSECURRENT: 0; TIME: 13:58:26; UPDATEDATE: 2024/01/31; UPDATETIME: 13:58:26; UPDATEUSER: sptcae13; USERCOMPTEXT3: TOSHIBA; VAL3: CRH01; ZENERVOLTAGEMAX: 0; ZENERVOLTAGEMIN: 0
D82 = D: ADSCNVFLAG: ON; ADSCOMPONENTNAME: D_D; ADSMODELNAME: s_CRH01_TE85L_AST_Q_; ALLGREEN: N:¢²¸; AUTHOR: sptcae13; CDMASTERCADCELG: MMK0167; COMP: GDM420000387; COMPONENTTYPE: 4; DATE: 2024/01/31; FNAPPROVALRESUG: 0:”­”Ô‚Ì‚Ý; FNCANCELLATIONG: 0:Žg—p‰Â; FNENVIRONMANTRG: N:¢²¸; FNLEADFREETHET1GT2GMCTH1: N_N_N; FORWARDVOLTAGEM: 0; FUNCN: GDM420000387; GATENO: 1; GCOUNT: 1; INSTANCENAME: cmp315; MAXAVERAGEFORWA: 1; MAXGCOUNT: 1; MAXREPETITIVEPE: 200; MAXREVERSEVOLTA: 0; MOUNTINGFORMSMD: SMD; OUMECLASSIFICATION: ¬p®¬fq/VbgLoA_CI[h; OUMEMAKER: TSB “ŒŽÅ; OUMEMAKERKATAMEI: CRH01(TE85L,AST,Q); PEAKFORWARDVOLT: 0; PMPRODUCTSTYPEG: DME; REVERSECURRENT: 0; TIME: 13:58:26; UPDATEDATE: 2024/01/31; UPDATETIME: 13:58:26; UPDATEUSER: sptcae13; USERCOMPTEXT3: TOSHIBA; VAL3: CRH01; ZENERVOLTAGEMAX: 0; ZENERVOLTAGEMIN: 0
D83 = SBD: ADSCNVFLAG: ON; ADSCOMPONENTNAME: D_SBD; ADSMODELNAME: s_CRS01_TE85R_Q_; ALLGREEN: N:¢²¸; CDMASTERCADCELG: MMK0167; COMPONENTTYPE: 4; FNAPPROVALRESUG: 5:bè(KR[h); FNCANCELLATIONG: 0:Žg—p‰Â; FNENVIRONMANTRG: N:¢²¸; FNLEADFREETHET1GT2GMCTH1: N_N_N; FORWARDVOLTAGEM: 0; FUNCN: K4200730; GCOUNT: 1; INSTANCENAME: cmp340; MAXAVERAGEFORWA: 1; MAXGCOUNT: 1; MAXREPETITIVEPE: 30; MAXREVERSEVOLTA: 0; MOUNTINGFORMSMD: SMD; OUMECLASSIFICATION: ¬p®¬fq/VbgLoA_CI[h; OUMEMAKER: TSB “ŒŽÅ; OUMEMAKERKATAMEI: CRS01(TE85R,Q); OUMEPARTTYPE: D; PEAKFORWARDVOLT: 360m; REVERSECURRENT: 1.5m; USERCOMPTEXT3: TOSHIBA; VAL3: CRS01; ZENERVOLTAGEMAX: 0; ZENERVOLTAGEMIN: 0
D84 = DMH: COMP: PRT_25; COMPONENTTYPE: 4; INSTANCENAME: cmp341; MAKER: TOSHIBA; NOTMOUNT: NOT MOUNT; USERCOMPTEXT3: TOSHIBA; VAL3: TBAT54
D90 = D: ADSCNVFLAG: ON; ADSCOMPONENTNAME: D_D; ADSMODELNAME: s_CRH01_TE85L_AST_Q_; ALLGREEN: N:¢²¸; AUTHOR: sptcae13; CDMASTERCADCELG: MMK0167; COMP: GDM420000387; COMPONENTTYPE: 4; DATE: 2024/01/31; FNAPPROVALRESUG: 0:”­”Ô‚Ì‚Ý; FNCANCELLATIONG: 0:Žg—p‰Â; FNENVIRONMANTRG: N:¢²¸; FNLEADFREETHET1GT2GMCTH1: N_N_N; FORWARDVOLTAGEM: 0; FUNCN: GDM420000387; GATENO: 1; GCOUNT: 1; INSTANCENAME: cmp302; MAXAVERAGEFORWA: 1; MAXGCOUNT: 1; MAXREPETITIVEPE: 200; MAXREVERSEVOLTA: 0; MOUNTINGFORMSMD: SMD; OUMECLASSIFICATION: ¬p®¬fq/VbgLoA_CI[h; OUMEMAKER: TSB “ŒŽÅ; OUMEMAKERKATAMEI: CRH01(TE85L,AST,Q); PEAKFORWARDVOLT: 0; PMPRODUCTSTYPEG: DME; REVERSECURRENT: 0; TIME: 13:58:26; UPDATEDATE: 2024/01/31; UPDATETIME: 13:58:26; UPDATEUSER: sptcae13; USERCOMPTEXT3: TOSHIBA; VAL3: CRH01; ZENERVOLTAGEMAX: 0; ZENERVOLTAGEMIN: 0
IC80 = UCC28910: COMPONENTTYPE: 4; GCOUNT: 1; INSTANCENAME: cmp300; MAXGCOUNT: 1
IC81 = LM317MDCY: ALLGREEN: N:¢²¸; CDMASTERCADCELG: MM0132; COMPONENTTYPE: 4; FNAPPROVALRESUG: 5:bè(KR[h); FNCANCELLATIONG: 0:Žg—p‰Â; FNENVIRONMANTRG: N:¢²¸; FNLEADFREETHET1GT2GMCTH1: N_N_N; FUNCTION: FXD; GCOUNT: 1; INSTANCENAME: cmp279; KIND: VRGL; MAXGCOUNT: 1; MOUNTINGFORMSMD: SMD; OUMECLASSIFICATION: M[^; OUMEMAKER: TII eLTXCXcc; OUMEMAKERKATAMEI: LM2937IMP-3.3; OUMEPARTTYPE: IC
IC82 = TCR1HF50B: COMPONENTTYPE: 4; INSTANCENAME: cmp335; USERCOMPTEXT3: TOSHIBA
R800 = R: COMPONENTTYPE: 4; INSTANCENAME: cmp288; SAVECOUNT: 0; SIZECODESMD: 3216; VAL1: 82k(J); VAL2: 250mW; VAL3: RK73B2BTTD823J
R801 = R: COMPONENTTYPE: 4; INSTANCENAME: cmp292; SAVECOUNT: 0; SIZECODESMD: 3216; VAL1: 82k(J); VAL2: 250mW; VAL3: RK73B2BTTD823J
R802 = R: ADSMODELNAME: s_RC0402FR_071KL; ALLGREEN: 0:O[; CDMASTERCADCELG: KC0005; COMPONENTTYPE: 4; FNAPPROVALRESUG: B:i(GREEN); FNCANCELLATIONG: 0:Žg—p‰Â; FNENVIRONMANTRG: 1:gpL(K§ÎÛO); FNLEADFREETHET1GT2GMCTH1: 2_2_N; GANSWERREV: 8; GCOUNT: 1; INSTANCENAME: cmp298; MAXGCOUNT: 1; MOUNTINGFORMSMD: SMD; NOMINALRESISTAN: 1K; OUMECLASSIFICATION: \ÊÀpÅèïRí; OUMEMAKER: YGO ƒ„ƒQƒI; OUMEMAKERKATAMEI: RC0402FR-071KL; PMPRODUCTSTYPEG: HD1; POWERRATING: 63m; QUADMODEL: RES_1K; RESISTANCETOLER: F; SAVECOUNT: 0; SIZECODESMD: 1005; VAL1: 10(J); VAL2: 63mW; VAL3: RK73K1ETP100J
R803 = R: COMP: GDM010004481; COMPONENTTYPE: 4; INSTANCENAME: cmp283; NOTMOUNT: NOT MOUNT; SAVECOUNT: 0; SIZECODESMD: 1005
R804 = R: ADSMODELNAME: s_RC0402FR_071KL; ALLGREEN: 0:O[; CDMASTERCADCELG: KC0005; COMPONENTTYPE: 4; FNAPPROVALRESUG: B:i(GREEN); FNCANCELLATIONG: 0:Žg—p‰Â; FNENVIRONMANTRG: 1:gpL(K§ÎÛO); FNLEADFREETHET1GT2GMCTH1: 2_2_N; GANSWERREV: 8; GCOUNT: 1; INSTANCENAME: cmp285; MAXGCOUNT: 1; MOUNTINGFORMSMD: SMD; NOMINALRESISTAN: 1K; OUMECLASSIFICATION: \ÊÀpÅèïRí; OUMEMAKER: YGO ƒ„ƒQƒI; OUMEMAKERKATAMEI: RC0402FR-071KL; PMPRODUCTSTYPEG: HD1; POWERRATING: 63m; QUADMODEL: RES_1K; RESISTANCETOLER: F; SAVECOUNT: 0; SIZECODESMD: 1005; VAL1: 2.7k(F); VAL2: 63mW; VAL3: RK73H1ETTP2701F
R806 = R: ADSMODELNAME: s_RC0402FR_071KL; ALLGREEN: 0:O[; CDMASTERCADCELG: KC0005; COMPONENTTYPE: 4; FNAPPROVALRESUG: B:i(GREEN); FNCANCELLATIONG: 0:Žg—p‰Â; FNENVIRONMANTRG: 1:gpL(K§ÎÛO); FNLEADFREETHET1GT2GMCTH1: 2_2_N; GANSWERREV: 8; GCOUNT: 1; INSTANCENAME: cmp306; MAXGCOUNT: 1; MOUNTINGFORMSMD: SMD; NOMINALRESISTAN: 1K; OUMECLASSIFICATION: \ÊÀpÅèïRí; OUMEMAKER: YGO ƒ„ƒQƒI; OUMEMAKERKATAMEI: RC0402FR-071KL; PMPRODUCTSTYPEG: HD1; POWERRATING: 63m; QUADMODEL: RES_1K; RESISTANCETOLER: F; SAVECOUNT: 0; SIZECODESMD: 1005; VAL1: 330k(J); VAL2: 63mW; VAL3: ERJ2GEJ334X
R807 = R: ADSMODELNAME: s_RC0402FR_071KL; ALLGREEN: 0:O[; CDMASTERCADCELG: KC0005; COMPONENTTYPE: 4; FNAPPROVALRESUG: B:i(GREEN); FNCANCELLATIONG: 0:Žg—p‰Â; FNENVIRONMANTRG: 1:gpL(K§ÎÛO); FNLEADFREETHET1GT2GMCTH1: 2_2_N; GANSWERREV: 8; GCOUNT: 1; INSTANCENAME: cmp296; MAXGCOUNT: 1; MOUNTINGFORMSMD: SMD; NOMINALRESISTAN: 1K; OUMECLASSIFICATION: \ÊÀpÅèïRí; OUMEMAKER: YGO ƒ„ƒQƒI; OUMEMAKERKATAMEI: RC0402FR-071KL; PMPRODUCTSTYPEG: HD1; POWERRATING: 63m; QUADMODEL: RES_1K; RESISTANCETOLER: F; SAVECOUNT: 0; SIZECODESMD: 1005; VAL1: 18k(F); VAL2: 63mW; VAL3: RK73H1ETTP1802F
R808 = R: ADSMODELNAME: s_RC0402FR_071KL; ALLGREEN: 0:O[; CDMASTERCADCELG: KC0005; COMPONENTTYPE: 4; FNAPPROVALRESUG: B:i(GREEN); FNCANCELLATIONG: 0:Žg—p‰Â; FNENVIRONMANTRG: 1:gpL(K§ÎÛO); FNLEADFREETHET1GT2GMCTH1: 2_2_N; GANSWERREV: 8; GCOUNT: 1; INSTANCENAME: cmp287; MAXGCOUNT: 1; MOUNTINGFORMSMD: SMD; NOMINALRESISTAN: 1K; OUMECLASSIFICATION: \ÊÀpÅèïRí; OUMEMAKER: YGO ƒ„ƒQƒI; OUMEMAKERKATAMEI: RC0402FR-071KL; PMPRODUCTSTYPEG: HD1; POWERRATING: 63m; QUADMODEL: RES_1K; RESISTANCETOLER: F; SAVECOUNT: 0; SIZECODESMD: 1005; VAL1: 47k(F); VAL2: 63mW; VAL3: RK73H1ETTP4702F
R809 = R: ADSMODELNAME: s_RC0402FR_071KL; ALLGREEN: 0:O[; CDMASTERCADCELG: KC0005; COMPONENTTYPE: 4; FNAPPROVALRESUG: B:i(GREEN); FNCANCELLATIONG: 0:Žg—p‰Â; FNENVIRONMANTRG: 1:gpL(K§ÎÛO); FNLEADFREETHET1GT2GMCTH1: 2_2_N; GANSWERREV: 8; GCOUNT: 1; INSTANCENAME: cmp303; MAXGCOUNT: 1; MOUNTINGFORMSMD: SMD; NOMINALRESISTAN: 1K; OUMECLASSIFICATION: \ÊÀpÅèïRí; OUMEMAKER: YGO ƒ„ƒQƒI; OUMEMAKERKATAMEI: RC0402FR-071KL; PMPRODUCTSTYPEG: HD1; POWERRATING: 63m; QUADMODEL: RES_1K; RESISTANCETOLER: F; SAVECOUNT: 0; SIZECODESMD: 1005; VAL1: 22(J); VAL2: 63mW; VAL3: ERJ2GEJ220X
R810 = R: ADSMODELNAME: s_RC0402FR_071KL; ALLGREEN: 0:O[; CDMASTERCADCELG: KC0005; COMPONENTTYPE: 4; FNAPPROVALRESUG: B:i(GREEN); FNCANCELLATIONG: 0:Žg—p‰Â; FNENVIRONMANTRG: 1:gpL(K§ÎÛO); FNLEADFREETHET1GT2GMCTH1: 2_2_N; GANSWERREV: 8; GCOUNT: 1; INSTANCENAME: cmp237; MAXGCOUNT: 1; MOUNTINGFORMSMD: SMD; NOMINALRESISTAN: 1K; OUMECLASSIFICATION: \ÊÀpÅèïRí; OUMEMAKER: YGO ƒ„ƒQƒI; OUMEMAKERKATAMEI: RC0402FR-071KL; PMPRODUCTSTYPEG: HD1; POWERRATING: 63m; QUADMODEL: RES_1K; RESISTANCETOLER: F; SAVECOUNT: 0; SIZECODESMD: 1005; VAL1: 270(F); VAL2: 63mW; VAL3: ERJ2RKF2700X
R811 = R: ADSMODELNAME: s_RC0402FR_071KL; ALLGREEN: 0:O[; CDMASTERCADCELG: KC0005; COMPONENTTYPE: 4; FNAPPROVALRESUG: B:i(GREEN); FNCANCELLATIONG: 0:Žg—p‰Â; FNENVIRONMANTRG: 1:gpL(K§ÎÛO); FNLEADFREETHET1GT2GMCTH1: 2_2_N; GANSWERREV: 8; GCOUNT: 1; INSTANCENAME: cmp236; MAXGCOUNT: 1; MOUNTINGFORMSMD: SMD; NOMINALRESISTAN: 1K; OUMECLASSIFICATION: \ÊÀpÅèïRí; OUMEMAKER: YGO ƒ„ƒQƒI; OUMEMAKERKATAMEI: RC0402FR-071KL; PMPRODUCTSTYPEG: HD1; POWERRATING: 63m; QUADMODEL: RES_1K; RESISTANCETOLER: F; SAVECOUNT: 0; SIZECODESMD: 1005; VAL1: 110k(F); VAL2: 63mW; VAL3: ERJ2RKF1103X
R812 = R: COMPONENTTYPE: 4; INSTANCENAME: cmp304; SAVECOUNT: 0; SIZECODESMD: 3216; VAL1: 150(J); VAL2: 250mW; VAL3: RK73B2BTTD151J
R813 = R: ADSCNVFLAG: ON; ADSCOMPONENTNAME: R_1005; ADSMODELNAME: s_RC0402FR_071KL; ALLGREEN: 0:O[; CDMASTERCADCELG: KC0005; CHIPSIZE: 1608; COMPONENTTYPE: 4; FNAPPROVALRESUG: B:i(GREEN); FNCANCELLATIONG: 0:Žg—p‰Â; FNENVIRONMANTRG: 1:gpL(K§ÎÛO); FNLEADFREETHET1GT2GMCTH1: 2_2_N; GANSWERREV: 8; GCOUNT: 1; ICX_PART_MODEL: RES_0; INSTANCENAME: cmp265; MAKER: KOA; MAXGCOUNT: 1; MOUNTINGFORMSMD: SMD; NOMINALRESISTAN: 1K; OUMECLASSIFICATION: \ÊÀpÅèïRí; OUMEMAKER: YGO ƒ„ƒQƒI; OUMEMAKERKATAMEI: RC0402FR-071KL; PMPRODUCTSTYPEG: HD1; POWERRATING: 63m; QUADMODEL: RES_1K; RESISTANCETOLER: F; SAVECOUNT: 0; SIZECODESMD: 1005; SQ_PART_MODEL: RES_0; VAL1: 1(J); VAL2: 63mW; VAL3: ERJ2GEJ1R0X
R814 = R: ADSMODELNAME: s_RC0402FR_071KL; ALLGREEN: 0:O[; CDMASTERCADCELG: KC0005; CHIPSIZE: 1608; COMPONENTTYPE: 4; FNAPPROVALRESUG: B:i(GREEN); FNCANCELLATIONG: 0:Žg—p‰Â; FNENVIRONMANTRG: 1:gpL(K§ÎÛO); FNLEADFREETHET1GT2GMCTH1: 2_2_N; GANSWERREV: 8; GCOUNT: 1; INSTANCENAME: cmp281; MAKER: PANASONIC; MAXGCOUNT: 1; MOUNTINGFORMSMD: SMD; NOMINALRESISTAN: 1K; OUMECLASSIFICATION: \ÊÀpÅèïRí; OUMEMAKER: YGO ƒ„ƒQƒI; OUMEMAKERKATAMEI: RC0402FR-071KL; PMPRODUCTSTYPEG: HD1; POWERRATING: 63m; QUADMODEL: RES_1K; RESISTANCETOLER: F; SAVECOUNT: 0; SIZECODESMD: 1005; VAL1: 100(J); VAL2: 63mW; VAL3: RK73K1ETP101J
R815 = R: ADSCNVFLAG: ON; ADSCOMPONENTNAME: R_1005; ADSMODELNAME: s_RC0402FR_071KL; ALLGREEN: 0:O[; CDMASTERCADCELG: KC0005; CHIPSIZE: 1608; COMPONENTTYPE: 4; FNAPPROVALRESUG: B:i(GREEN); FNCANCELLATIONG: 0:Žg—p‰Â; FNENVIRONMANTRG: 1:gpL(K§ÎÛO); FNLEADFREETHET1GT2GMCTH1: 2_2_N; GANSWERREV: 8; GCOUNT: 1; ICX_PART_MODEL: RES_0; INSTANCENAME: cmp259; MAKER: KOA; MAXGCOUNT: 1; MOUNTINGFORMSMD: SMD; NOMINALRESISTAN: 1K; OUMECLASSIFICATION: \ÊÀpÅèïRí; OUMEMAKER: YGO ƒ„ƒQƒI; OUMEMAKERKATAMEI: RC0402FR-071KL; PMPRODUCTSTYPEG: HD1; POWERRATING: 63m; QUADMODEL: RES_1K; RESISTANCETOLER: F; SAVECOUNT: 0; SIZECODESMD: 1005; SQ_PART_MODEL: RES_0; VAL1: 0; VAL2: 63mW; VAL3: RK73Z1ETTP
R832 = R: ADSCNVFLAG: ON; ADSCOMPONENTNAME: R_1005; ADSMODELNAME: s_RC0402FR_071KL; ALLGREEN: 0:O[; CDMASTERCADCELG: KC0005; CHIPSIZE: 1608; COMPONENTTYPE: 4; FNAPPROVALRESUG: B:i(GREEN); FNCANCELLATIONG: 0:Žg—p‰Â; FNENVIRONMANTRG: 1:gpL(K§ÎÛO); FNLEADFREETHET1GT2GMCTH1: 2_2_N; GANSWERREV: 8; GCOUNT: 1; ICX_PART_MODEL: RES_0; INSTANCENAME: cmp343; MAKER: KOA; MAXGCOUNT: 1; MOUNTINGFORMSMD: SMD; NOMINALRESISTAN: 1K; OUMECLASSIFICATION: \ÊÀpÅèïRí; OUMEMAKER: YGO ƒ„ƒQƒI; OUMEMAKERKATAMEI: RC0402FR-071KL; PMPRODUCTSTYPEG: HD1; POWERRATING: 63m; QUADMODEL: RES_1K; RESISTANCETOLER: F; SAVECOUNT: 0; SIZECODESMD: 1005; SQ_PART_MODEL: RES_0; VAL1: 1(J); VAL2: 63mW; VAL3: ERJ2GEJ1R0X
T8 = YB_03317A: COMPONENTTYPE: 4; FUNCN: YB-03317A; GCOUNT: 1; INSTANCENAME: cmp284; MAXGCOUNT: 1; VAL1: 140:15:17; VAL3: TAM-EE16-150-15
TP82 = TP: AUTHOR: sptcae13; COMP: PRT_44; COMPONENTTYPE: 4; DATE: 2024/01/31; INSTANCENAME: cmp242; MAKER: MAC8; TIME: 13:58:25; UPDATEDATE: 2024/01/31; UPDATETIME: 13:58:25; UPDATEUSER: sptcae13; VAL3: HK-2-S
TP83 = TP: AUTHOR: sptcae13; COMP: PRT_44; COMPONENTKIND: 127; COMPONENTTYPE: 4; DATE: 2024/01/31; INSTANCENAME: cmp344; MAKER: MAC8; TIME: 13:58:25; UPDATEDATE: 2024/01/31; UPDATETIME: 13:58:25; UPDATEUSER: sptcae13; VAL3: HK-2-S
U?#1 = WAKU_DEF100: COMPONENTTYPE: 2; DATE: 2024/02/05; DESIGNED: TOSHIBA; DRAWINGNUMBER: RD240-SCHEMATIC-01; FUNCTION: Control Power; INSTANCENAME: cmp184; PAGENUMBER: 8; REVISION: 01; SHEETNUMBER: 8/9; SHTSAVECOUNT: 92; TITLE: 1.6 kW Server Power Supply / (Upgraded); UPDATEDATE: 2024/02/07; UPDATETIME: 11:17:33; UPDATEUSER: t5459927
C59 = C: ADSCNVFLAG: ON; ADSCOMPONENTNAME: C_1005; ADSMODELNAME: s_UMK105BJ222KV_F; AUTHOR: sptcae13; CAPACITANCETOLE: K; CDMASTERCADCELG: KC0005; CHIPSIZE: 1005; COMP: PRT_52; COMPONENTTYPE: 4; DATE: 2024/01/31; FNLEADFREETHET1GT2GMCTH1: 2_0_N; GCOUNT: 1; ICX_PART_MODEL: CON_2.2N; INSTANCENAME: cmp202; MAKER: TDK; MAXGCOUNT: 1; NOMINALCAPACITA: 2.2n; OUMECLASSIFICATION: ƒZƒ‰ƒ~ƒbƒNƒRƒ“ƒfƒ“ƒT; OUMEMAKER: TYD ‘¾—z—U“d; OUMEMAKERKATAMEI: UMK105BJ222KV-F; PMPRODUCTSTYPEG: HD1-PC1; QUADMODEL: CON_2.2N; RATEDVOLTAGE: 50; SAVECOUNT: 0; SIZECODESMD: 1005; SQ_PART_MODEL: CON_2.2N; TEMPCHARACTERI2: B; TIME: 13:58:26; UPDATEDATE: 2024/01/31; UPDATETIME: 13:58:26; UPDATEUSER: sptcae13; VAL1: 2.2nF(K); VAL2: 50V; VAL3: UMK105BJ222KV-F
C92 = C: ADSMODELNAME: s_GRM155R71E104KE14D; AUTHOR: sptcae13; CAPACITANCETOLE: K; CDMASTERCADCELG: KC0005; CHIPSIZE: 1005; COMP: PRT_52; COMPONENTTYPE: 4; DATE: 2024/01/31; FNLEADFREETHET1GT2GMCTH1: N_N_N; GCOUNT: 1; INSTANCENAME: cmp235; MAKER: TDK; MAXGCOUNT: 1; NOMINALCAPACITA: 100n; OUMECLASSIFICATION: ƒZƒ‰ƒ~ƒbƒNƒRƒ“ƒfƒ“ƒT; OUMEMAKER: MRT ºc»ì; OUMEMAKERKATAMEI: GRM155R71E104KE14D; QUADMODEL: CON_100N; RATEDVOLTAGE: 25; SAVECOUNT: 0; SIZECODESMD: 1005; TIME: 13:58:26; UPDATEDATE: 2024/01/31; UPDATETIME: 13:58:26; UPDATEUSER: sptcae13; VAL1: 100nF(K); VAL2: 25V; VAL3: C1005X7R1E104K050BB
C93 = C: ADSMODELNAME: s_GRM155R71E104KE14D; AUTHOR: sptcae13; CAPACITANCETOLE: K; CDMASTERCADCELG: KC0005; CHIPSIZE: 1005; COMP: PRT_52; COMPONENTTYPE: 4; DATE: 2024/01/31; FNLEADFREETHET1GT2GMCTH1: N_N_N; GCOUNT: 1; INSTANCENAME: cmp242; MAKER: TDK; MAXGCOUNT: 1; NOMINALCAPACITA: 100n; OUMECLASSIFICATION: ƒZƒ‰ƒ~ƒbƒNƒRƒ“ƒfƒ“ƒT; OUMEMAKER: MRT ºc»ì; OUMEMAKERKATAMEI: GRM155R71E104KE14D; QUADMODEL: CON_100N; RATEDVOLTAGE: 25; SAVECOUNT: 0; SIZECODESMD: 1005; TIME: 13:58:26; UPDATEDATE: 2024/01/31; UPDATETIME: 13:58:26; UPDATEUSER: sptcae13; VAL1: 100nF(K); VAL2: 25V; VAL3: C1005X7R1E104K050BB
C94 = C: ADSMODELNAME: s_GRM155R71E104KE14D; AUTHOR: sptcae13; CAPACITANCETOLE: K; CDMASTERCADCELG: KC0005; CHIPSIZE: 1005; COMP: PRT_52; COMPONENTTYPE: 4; DATE: 2024/01/31; FNLEADFREETHET1GT2GMCTH1: N_N_N; GCOUNT: 1; INSTANCENAME: cmp236; MAKER: TDK; MAXGCOUNT: 1; NOMINALCAPACITA: 100n; OUMECLASSIFICATION: ƒZƒ‰ƒ~ƒbƒNƒRƒ“ƒfƒ“ƒT; OUMEMAKER: MRT ºc»ì; OUMEMAKERKATAMEI: GRM155R71E104KE14D; QUADMODEL: CON_100N; RATEDVOLTAGE: 25; SAVECOUNT: 0; SIZECODESMD: 1005; TIME: 13:58:26; UPDATEDATE: 2024/01/31; UPDATETIME: 13:58:26; UPDATEUSER: sptcae13; VAL1: 100nF(K); VAL2: 25V; VAL3: C1005X7R1E104K050BB
C100 = C: ADSMODELNAME: s_GRM155R71H222KA01D; AUTHOR: sptcae13; CAPACITANCETOLE: K; CDMASTERCADCELG: KC0005; CHIPSIZE: 1005; COMP: PRT_52; COMPONENTTYPE: 4; DATE: 2024/01/31; FNLEADFREETHET1GT2GMCTH1: 2_0_N; GCOUNT: 1; INSTANCENAME: cmp147; MAKER: TDK; MAXGCOUNT: 1; NOMINALCAPACITA: 2.2n; OUMECLASSIFICATION: ƒZƒ‰ƒ~ƒbƒNƒRƒ“ƒfƒ“ƒT; OUMEMAKER: MRT ºc»ì; OUMEMAKERKATAMEI: GRM155R71H222KA01D; PMPRODUCTSTYPEG: HD1; QUADMODEL: CON_2.2N; RATEDVOLTAGE: 50; SAVECOUNT: 0; SIZECODESMD: 1005; TIME: 13:58:26; UPDATEDATE: 2024/01/31; UPDATETIME: 13:58:26; UPDATEUSER: sptcae13; VAL1: 100nF(K); VAL2: 25V; VAL3: C1005X7R1E104K050BB
CN6 = CN1: AUTHOR: sptcae13; COMP: PRT_38; COMPONENTTYPE: 4; DATE: 2024/01/31; INSTANCENAME: cmp249; MAKER: OSADA; SAVECOUNT: 0; TIME: 13:58:24; UPDATEDATE: 2024/01/31; UPDATETIME: 13:58:24; UPDATEUSER: sptcae13; VAL3: OP-1100
CN7 = CN1: AUTHOR: sptcae13; COMP: PRT_38; COMPONENTTYPE: 4; DATE: 2024/01/31; INSTANCENAME: cmp250; MAKER: OSADA; SAVECOUNT: 0; TIME: 13:58:24; UPDATEDATE: 2024/01/31; UPDATETIME: 13:58:24; UPDATEUSER: sptcae13; VAL3: OP-1100
CN8 = CN2: AUTHOR: sptcae13; COMP: PRT_42; COMPONENTTYPE: 4; DATE: 2024/01/31; INSTANCENAME: cmp247; MAKER: MOLEX; SAVECOUNT: 0; TIME: 13:58:24; UPDATEDATE: 2024/01/31; UPDATETIME: 13:58:24; UPDATEUSER: sptcae13; VAL3: 5045-02A
CN9 = CN2: AUTHOR: sptcae13; COMP: PRT_42; COMPONENTTYPE: 4; DATE: 2024/01/31; INSTANCENAME: cmp258; MAKER: MOLEX; SAVECOUNT: 0; TIME: 13:58:24; UPDATEDATE: 2024/01/31; UPDATETIME: 13:58:24; UPDATEUSER: sptcae13; VAL3: 5045-02A
IC8 = L2412: COMP: PRT_62; COMPONENTTYPE: 4; INSTANCENAME: cmp36; MAKER: TEXAS; VAL3: TPS2412D
Q15 = TPHR6503PL1_8PIN: ADSMODELNAME: s_TK040N65Z; ALLGREEN: N:¢²¸; CDMASTERCADCELG: RDP1002; COMP: TPHR6503PL1(LQ); COMPONENTTYPE: 4; FNAPPROVALRESUG: 5:bè(KR[h); FNCANCELLATIONG: 0:Žg—p‰Â; FNENVIRONMANTRG: N:¢²¸; FNLEADFREETHET1GT2GMCTH1: N_N_N; FUNCN: TPHR6503PL1; GCOUNT: 1; INSTANCENAME: cmp68; MAKER: TOSHIBA; MAXCBVOLTAGE: 0; MAXCEVOLTAGE: 0; MAXCOLLECTORCUR: 0; MAXDRAINCURRENT: 57; MAXDSVOLTAGE: 650; MAXEBVOLTAGE: 0; MAXGATECURRENT: 0; MAXGCOUNT: 1; MAXGDVOLTAGE: 0; MAXGSVOLTAGE: 30; MOUNTINGFORMSMD: DIP; OUMECLASSIFICATION: Nƒ`ƒƒƒ“ƒlƒ‹MOS-FET; OUMEMAKER: TSB “ŒŽÅ; OUMEMAKERKATAMEI: TK040N65Z; OUMEPARTTYPE: Q; USERCOMPTEXT3: TOSHIBA; VAL3: TPHR6503PL1
Q16 = TPHR6503PL1_8PIN: ADSMODELNAME: s_TK040N65Z; ALLGREEN: N:¢²¸; CDMASTERCADCELG: RDP1002; COMP: TPHR6503PL1(LQ); COMPONENTTYPE: 4; FNAPPROVALRESUG: 5:bè(KR[h); FNCANCELLATIONG: 0:Žg—p‰Â; FNENVIRONMANTRG: N:¢²¸; FNLEADFREETHET1GT2GMCTH1: N_N_N; FUNCN: TPHR6503PL1; GCOUNT: 1; INSTANCENAME: cmp69; MAKER: TOSHIBA; MAXCBVOLTAGE: 0; MAXCEVOLTAGE: 0; MAXCOLLECTORCUR: 0; MAXDRAINCURRENT: 57; MAXDSVOLTAGE: 650; MAXEBVOLTAGE: 0; MAXGATECURRENT: 0; MAXGCOUNT: 1; MAXGDVOLTAGE: 0; MAXGSVOLTAGE: 30; MOUNTINGFORMSMD: DIP; OUMECLASSIFICATION: Nƒ`ƒƒƒ“ƒlƒ‹MOS-FET; OUMEMAKER: TSB “ŒŽÅ; OUMEMAKERKATAMEI: TK040N65Z; OUMEPARTTYPE: Q; USERCOMPTEXT3: TOSHIBA; VAL3: TPHR6503PL1
Q17 = TPHR6503PL1_8PIN: ADSMODELNAME: s_TK040N65Z; ALLGREEN: N:¢²¸; CDMASTERCADCELG: RDP1002; COMP: TPHR6503PL1(LQ); COMPONENTTYPE: 4; FNAPPROVALRESUG: 5:bè(KR[h); FNCANCELLATIONG: 0:Žg—p‰Â; FNENVIRONMANTRG: N:¢²¸; FNLEADFREETHET1GT2GMCTH1: N_N_N; FUNCN: TPHR6503PL1; GCOUNT: 1; INSTANCENAME: cmp66; MAKER: TOSHIBA; MAXCBVOLTAGE: 0; MAXCEVOLTAGE: 0; MAXCOLLECTORCUR: 0; MAXDRAINCURRENT: 57; MAXDSVOLTAGE: 650; MAXEBVOLTAGE: 0; MAXGATECURRENT: 0; MAXGCOUNT: 1; MAXGDVOLTAGE: 0; MAXGSVOLTAGE: 30; MOUNTINGFORMSMD: DIP; OUMECLASSIFICATION: Nƒ`ƒƒƒ“ƒlƒ‹MOS-FET; OUMEMAKER: TSB “ŒŽÅ; OUMEMAKERKATAMEI: TK040N65Z; OUMEPARTTYPE: Q; USERCOMPTEXT3: TOSHIBA; VAL3: TPHR6503PL1
Q18 = TPHR6503PL1_8PIN: ADSMODELNAME: s_TK040N65Z; ALLGREEN: N:¢²¸; CDMASTERCADCELG: RDP1002; COMP: TPHR6503PL1(LQ); COMPONENTTYPE: 4; FNAPPROVALRESUG: 5:bè(KR[h); FNCANCELLATIONG: 0:Žg—p‰Â; FNENVIRONMANTRG: N:¢²¸; FNLEADFREETHET1GT2GMCTH1: N_N_N; FUNCN: TPHR6503PL1; GCOUNT: 1; INSTANCENAME: cmp67; MAKER: TOSHIBA; MAXCBVOLTAGE: 0; MAXCEVOLTAGE: 0; MAXCOLLECTORCUR: 0; MAXDRAINCURRENT: 57; MAXDSVOLTAGE: 650; MAXEBVOLTAGE: 0; MAXGATECURRENT: 0; MAXGCOUNT: 1; MAXGDVOLTAGE: 0; MAXGSVOLTAGE: 30; MOUNTINGFORMSMD: DIP; OUMECLASSIFICATION: Nƒ`ƒƒƒ“ƒlƒ‹MOS-FET; OUMEMAKER: TSB “ŒŽÅ; OUMEMAKERKATAMEI: TK040N65Z; OUMEPARTTYPE: Q; USERCOMPTEXT3: TOSHIBA; VAL3: TPHR6503PL1
Q19 = TPHR6503PL1_8PIN: ADSMODELNAME: s_TK040N65Z; ALLGREEN: N:¢²¸; CDMASTERCADCELG: RDP1002; COMP: TPHR6503PL1(LQ); COMPONENTTYPE: 4; FNAPPROVALRESUG: 5:bè(KR[h); FNCANCELLATIONG: 0:Žg—p‰Â; FNENVIRONMANTRG: N:¢²¸; FNLEADFREETHET1GT2GMCTH1: N_N_N; FUNCN: TPHR6503PL1; GCOUNT: 1; INSTANCENAME: cmp29; MAKER: TOSHIBA; MAXCBVOLTAGE: 0; MAXCEVOLTAGE: 0; MAXCOLLECTORCUR: 0; MAXDRAINCURRENT: 57; MAXDSVOLTAGE: 650; MAXEBVOLTAGE: 0; MAXGATECURRENT: 0; MAXGCOUNT: 1; MAXGDVOLTAGE: 0; MAXGSVOLTAGE: 30; MOUNTINGFORMSMD: DIP; OUMECLASSIFICATION: Nƒ`ƒƒƒ“ƒlƒ‹MOS-FET; OUMEMAKER: TSB “ŒŽÅ; OUMEMAKERKATAMEI: TK040N65Z; OUMEPARTTYPE: Q; USERCOMPTEXT3: TOSHIBA; VAL3: TPHR6503PL1
Q20 = TPHR6503PL1_8PIN: COMP: TPHR6503PL1(LQ); COMPONENTTYPE: 4; INSTANCENAME: cmp273; VAL3: TPHR6503PL1
Q21 = TPHR6503PL1_8PIN: COMP: TPHR6503PL1(LQ); COMPONENTTYPE: 4; INSTANCENAME: cmp274; VAL3: TPHR6503PL1
Q22 = TPHR6503PL1_8PIN: COMP: TPHR6503PL1(LQ); COMPONENTTYPE: 4; INSTANCENAME: cmp275; VAL3: TPHR6503PL1
Q23 = TPHR6503PL1_8PIN: COMP: TPHR6503PL1(LQ); COMPONENTTYPE: 4; INSTANCENAME: cmp277; VAL3: TPHR6503PL1
Q24 = TPHR6503PL1_8PIN: COMP: TPHR6503PL1(LQ); COMPONENTTYPE: 4; INSTANCENAME: cmp278; VAL3: TPHR6503PL1
R6 = R: ADSMODELNAME: s_RC0603JR_072R2L; CDMASTERCADCELG: KC0008; CHIPSIZE: 1608; COMPONENTTYPE: 4; FNLEADFREETHET1GT2GMCTH1: 2_1_N; GCOUNT: 1; INSTANCENAME: cmp232; MAKER: KAMAYA; MAXGCOUNT: 1; MOUNTINGFORMSMD: SMD; NOMINALRESISTAN: 2.2; OUMECLASSIFICATION: \ÊÀpÅèïRí; OUMEMAKER: YGO ƒ„ƒQƒI; OUMEMAKERKATAMEI: RC0603JR-072R2L; PMPRODUCTSTYPEG: PC1; POWERRATING: 100m; QUADMODEL: RES_2.2; RESISTANCETOLER: J; SAVECOUNT: 0; SIZECODESMD: 1608; VAL1: 2.2(J); VAL2: 100mW; VAL3: RMC1/16 - 2R2J TP
R204 = R: ADSMODELNAME: s_RC0402FR_071KL; ALLGREEN: 0:O[; CDMASTERCADCELG: KC0005; CHIPSIZE: 1608; COMPONENTTYPE: 4; FNAPPROVALRESUG: B:i(GREEN); FNCANCELLATIONG: 0:Žg—p‰Â; FNENVIRONMANTRG: 1:gpL(K§ÎÛO); FNLEADFREETHET1GT2GMCTH1: 2_2_N; GANSWERREV: 8; GCOUNT: 1; INSTANCENAME: cmp243; MAKER: KOA; MAXGCOUNT: 1; MOUNTINGFORMSMD: SMD; NOMINALRESISTAN: 1K; OUMECLASSIFICATION: \ÊÀpÅèïRí; OUMEMAKER: YGO ƒ„ƒQƒI; OUMEMAKERKATAMEI: RC0402FR-071KL; PMPRODUCTSTYPEG: HD1; POWERRATING: 63m; QUADMODEL: RES_1K; RESISTANCETOLER: F; SAVECOUNT: 0; SIZECODESMD: 1005; VAL1: 0; VAL2: 63mW; VAL3: RK73Z1ETTP
R205 = R: ADSMODELNAME: s_RC0402FR_071KL; ALLGREEN: 0:O[; CDMASTERCADCELG: KC0005; CHIPSIZE: 1608; COMPONENTTYPE: 4; FNAPPROVALRESUG: B:i(GREEN); FNCANCELLATIONG: 0:Žg—p‰Â; FNENVIRONMANTRG: 1:gpL(K§ÎÛO); FNLEADFREETHET1GT2GMCTH1: 2_2_N; GANSWERREV: 8; GCOUNT: 1; INSTANCENAME: cmp237; MAKER: KOA; MAXGCOUNT: 1; MOUNTINGFORMSMD: SMD; NOMINALRESISTAN: 1K; OUMECLASSIFICATION: \ÊÀpÅèïRí; OUMEMAKER: YGO ƒ„ƒQƒI; OUMEMAKERKATAMEI: RC0402FR-071KL; PMPRODUCTSTYPEG: HD1; POWERRATING: 63m; QUADMODEL: RES_1K; RESISTANCETOLER: F; SAVECOUNT: 0; SIZECODESMD: 1005; VAL1: 0; VAL2: 63mW; VAL3: RK73Z1ETTP
R206 = R: ADSMODELNAME: s_RC0402FR_071KL; ALLGREEN: 0:O[; CDMASTERCADCELG: KC0005; CHIPSIZE: 1608; COMPONENTTYPE: 4; FNAPPROVALRESUG: B:i(GREEN); FNCANCELLATIONG: 0:Žg—p‰Â; FNENVIRONMANTRG: 1:gpL(K§ÎÛO); FNLEADFREETHET1GT2GMCTH1: 2_2_N; GANSWERREV: 8; GCOUNT: 1; INSTANCENAME: cmp244; MAKER: KOA; MAXGCOUNT: 1; MOUNTINGFORMSMD: SMD; NOMINALRESISTAN: 1K; OUMECLASSIFICATION: \ÊÀpÅèïRí; OUMEMAKER: YGO ƒ„ƒQƒI; OUMEMAKERKATAMEI: RC0402FR-071KL; PMPRODUCTSTYPEG: HD1; POWERRATING: 63m; QUADMODEL: RES_1K; RESISTANCETOLER: F; SAVECOUNT: 0; SIZECODESMD: 1005; VAL1: 0; VAL2: 63mW; VAL3: RK73Z1ETTP
TP28 = TP: AUTHOR: sptcae13; COMP: PRT_44; COMPONENTTYPE: 4; DATE: 2024/01/31; INSTANCENAME: cmp185; MAKER: MAC8; TIME: 13:58:25; UPDATEDATE: 2024/01/31; UPDATETIME: 13:58:25; UPDATEUSER: sptcae13; VAL3: HK-2-S
TP31 = TP: AUTHOR: sptcae13; COMP: PRT_44; COMPONENTTYPE: 4; DATE: 2024/01/31; INSTANCENAME: cmp188; MAKER: MAC8; TIME: 13:58:25; UPDATEDATE: 2024/01/31; UPDATETIME: 13:58:25; UPDATEUSER: sptcae13; VAL3: HK-2-S
U?#9 = WAKU_DEF100: COMPONENTTYPE: 2; DATE: 2024/02/05; DESIGNED: TOSHIBA; DRAWINGNUMBER: RD240-SCHEMATIC-01; FUNCTION: ORing & 12V Output; INSTANCENAME: cmp255; PAGENUMBER: 9; REVISION: 01; SHEETNUMBER: 9/9; SHTSAVECOUNT: 32; TITLE: 1.6 kW Server Power Supply / (Upgraded); UPDATEDATE: 2024/02/07; UPDATETIME: 09:42:59; UPDATEUSER: t5459927

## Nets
P12V: C92.2 C93.2 C100.2 CN6.1 IC8.1 IC8.6 Q15.5 Q15.6 Q15.7 Q15.8 Q16.5 Q16.6 Q16.7 Q16.8 Q17.5 Q17.6 Q17.7 Q17.8 Q18.5 Q18.6 Q18.7 Q18.8 Q19.5 Q19.6 Q19.7 Q19.8 Q20.5 Q20.6 Q20.7 Q20.8 Q21.5 Q21.6 Q21.7 Q21.8 Q22.5 Q22.6 Q22.7 Q22.8 Q23.5 Q23.6 Q23.7 Q23.8 Q24.5 Q24.6 Q24.7 Q24.8
VCC5R0_1: C103.2 IC12.16 ; also on sheet 7
VCC5R0_2: C104.2 IC12.1 R815.2
VCC12R0_1: R832.1 TP82.1 ; also on sheet 6 7 8 9
VCC12R0_2: R813.2 R814.1 TP83.1 ; also on sheet 4 5
CONN004: C59.2 CN8.1 CN9.1 IC8.7 Q15.1 Q15.2 Q15.3 Q16.1 Q16.2 Q16.3 Q17.1 Q17.2 Q17.3 Q18.1 Q18.2 Q18.3 Q19.1 Q19.2 Q19.3 Q20.1 Q20.2 Q20.3 Q21.1 Q21.2 Q21.3 Q22.1 Q22.2 Q22.3 Q23.1 Q23.2 Q23.3 Q24.1 Q24.2 Q24.3 TP31.1 ; also on sheet 4 5
FG6: C93.1 C94.2 R205.1 R206.1
FG7: R204.1
LGND: C92.1 C94.1 C100.1 C104.1 C816.1 C817.1 C818.1 CN7.1 CN8.2 CN9.2 IC8.3 IC8.4 IC12.2 IC12.8 IC82.2 R204.2 R205.2 R206.2 R812.1 R817.1 R821.1 R825.1 R829.1 T8.7 ; also on sheet 4 5 6 9
OUTA1: IC12.14 ; also on sheet 6
OUTA2: R816.2 ; also on sheet 4
OUTB1: IC12.13 ; also on sheet 6
OUTB2: R820.2 ; also on sheet 4
OUTC1: IC12.12 ; also on sheet 6
OUTC2: R824.2 ; also on sheet 4
OUTD1: IC12.11 ; also on sheet 6
OUTD2: R828.2 ; also on sheet 4
PFC_OUT: C800.2 C801.2 R800.2 T8.1 ; also on sheet 6 7 8
PN: C103.1 C800.1 C802.1 C803.1 C804.1 C805.1 C806.1 C808.1 IC12.9 IC12.15 IC80.1 IC80.2 IC80.3 R803.1 R804.1 R806.1 R807.1 R811.1 T8.4 ; also on sheet 6 7 8 9
SIG122: C59.1 IC8.8
SIG136: IC8.5 R6.1
SIG141: Q15.4 Q16.4 Q17.4 Q18.4 Q19.4 Q20.4 Q21.4 Q22.4 Q23.4 Q24.4 R6.2 TP28.1
SIG00733: R828.1 R829.2 R831.1
SIG00734: R824.1 R825.2 R827.1
SIG00735: R820.1 R821.2 R823.1
SIG00736: R816.1 R817.2 R819.1
SIG00737: IC12.3 R819.2
SIG00738: IC12.4 R823.2
SIG00739: IC12.5 R827.2
SIG00740: IC12.6 R831.2
SIG00821: C805.2 D84.A IC81.1 R810.1 R811.2
SIG00822: C804.2 C808.2 D82.C D83.C IC81.3
SIG00823: C818.2 IC82.5 R815.1
SIG00826: C817.2 IC82.1 IC82.3 R814.2
SIG00828: D81.C R809.2
SIG00829: C815.2 D90.A T8.9
SIG00830: C802.2 C803.2 IC80.6 R809.1
SIG00831: IC80.5 R806.2 R807.2 R808.1
SIG00832: IC80.4 R803.2 R804.2
SIG00833: C801.1 R801.1 R802.1
SIG00834: D80.A IC80.8 T8.3
SIG00835: D80.C R802.2
SIG00836: R800.1 R801.2
SIG00837: C815.1 R812.2
SIG00838: D81.A D82.A R808.2 T8.5
SIG00839: C806.2 D83.A D84.C IC81.2 IC81.4 R810.2 R832.2
SIG00840: C816.2 D90.C R813.1

Not connected (* = marked no-connect by the designer): D84 NC; IC8 2; IC12 7 10; IC82 4; T8 2 8

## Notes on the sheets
sheet 1
- Q15`Q24:TPHR6503PL1
- 12V output
- for Fan power supply
- Housing(for CN8):51191-0200
- for Fan power supply
- Housing(for CN9):51191-0200
sheet 2
- Primary
- Secondary
- 140turn
- 4mH
- 15turn
- for current
  measurement
- for current
  measurement
- 17turn
- for current
  measurement
sheet 3
- Secondary
- Primary
